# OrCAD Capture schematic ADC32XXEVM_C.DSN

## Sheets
1 SH04 - AMPLIFIER: size B; title: AMPLIFIER; rev: C; note: ADC32XXEVM
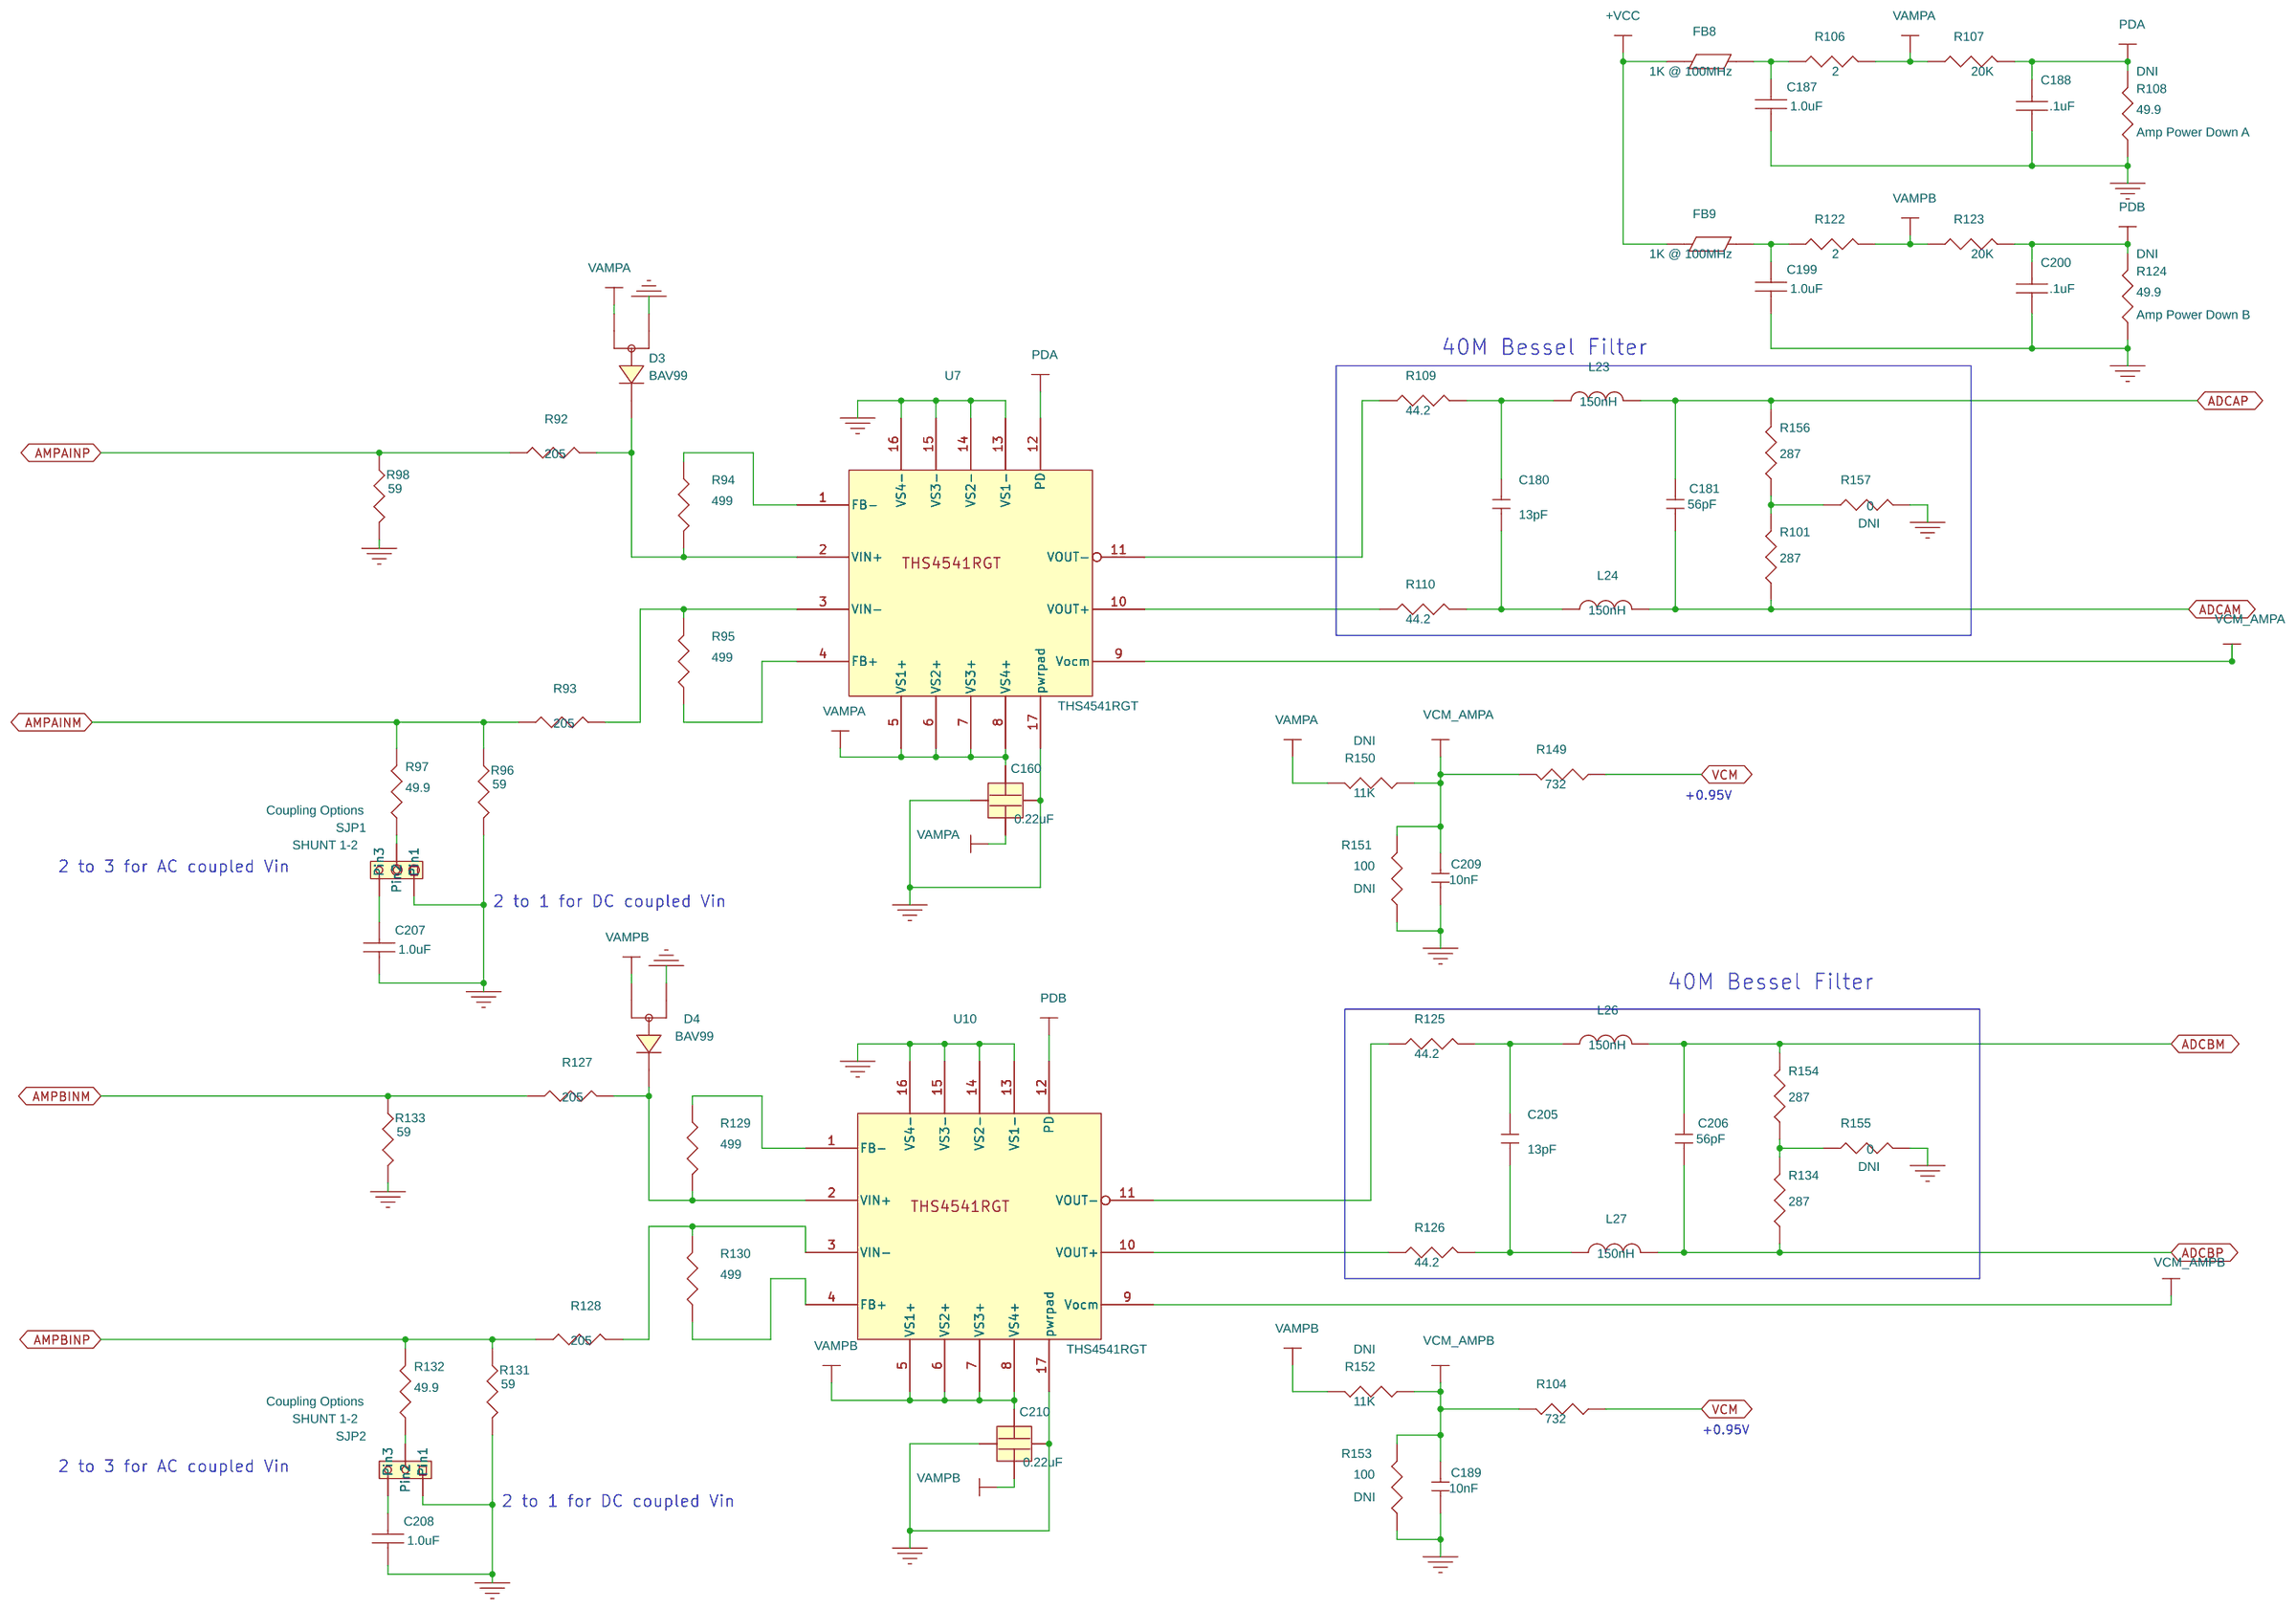
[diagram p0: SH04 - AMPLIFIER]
2 SH01 - COVER: title: ADC34J4X; note: ADC32XX EVM
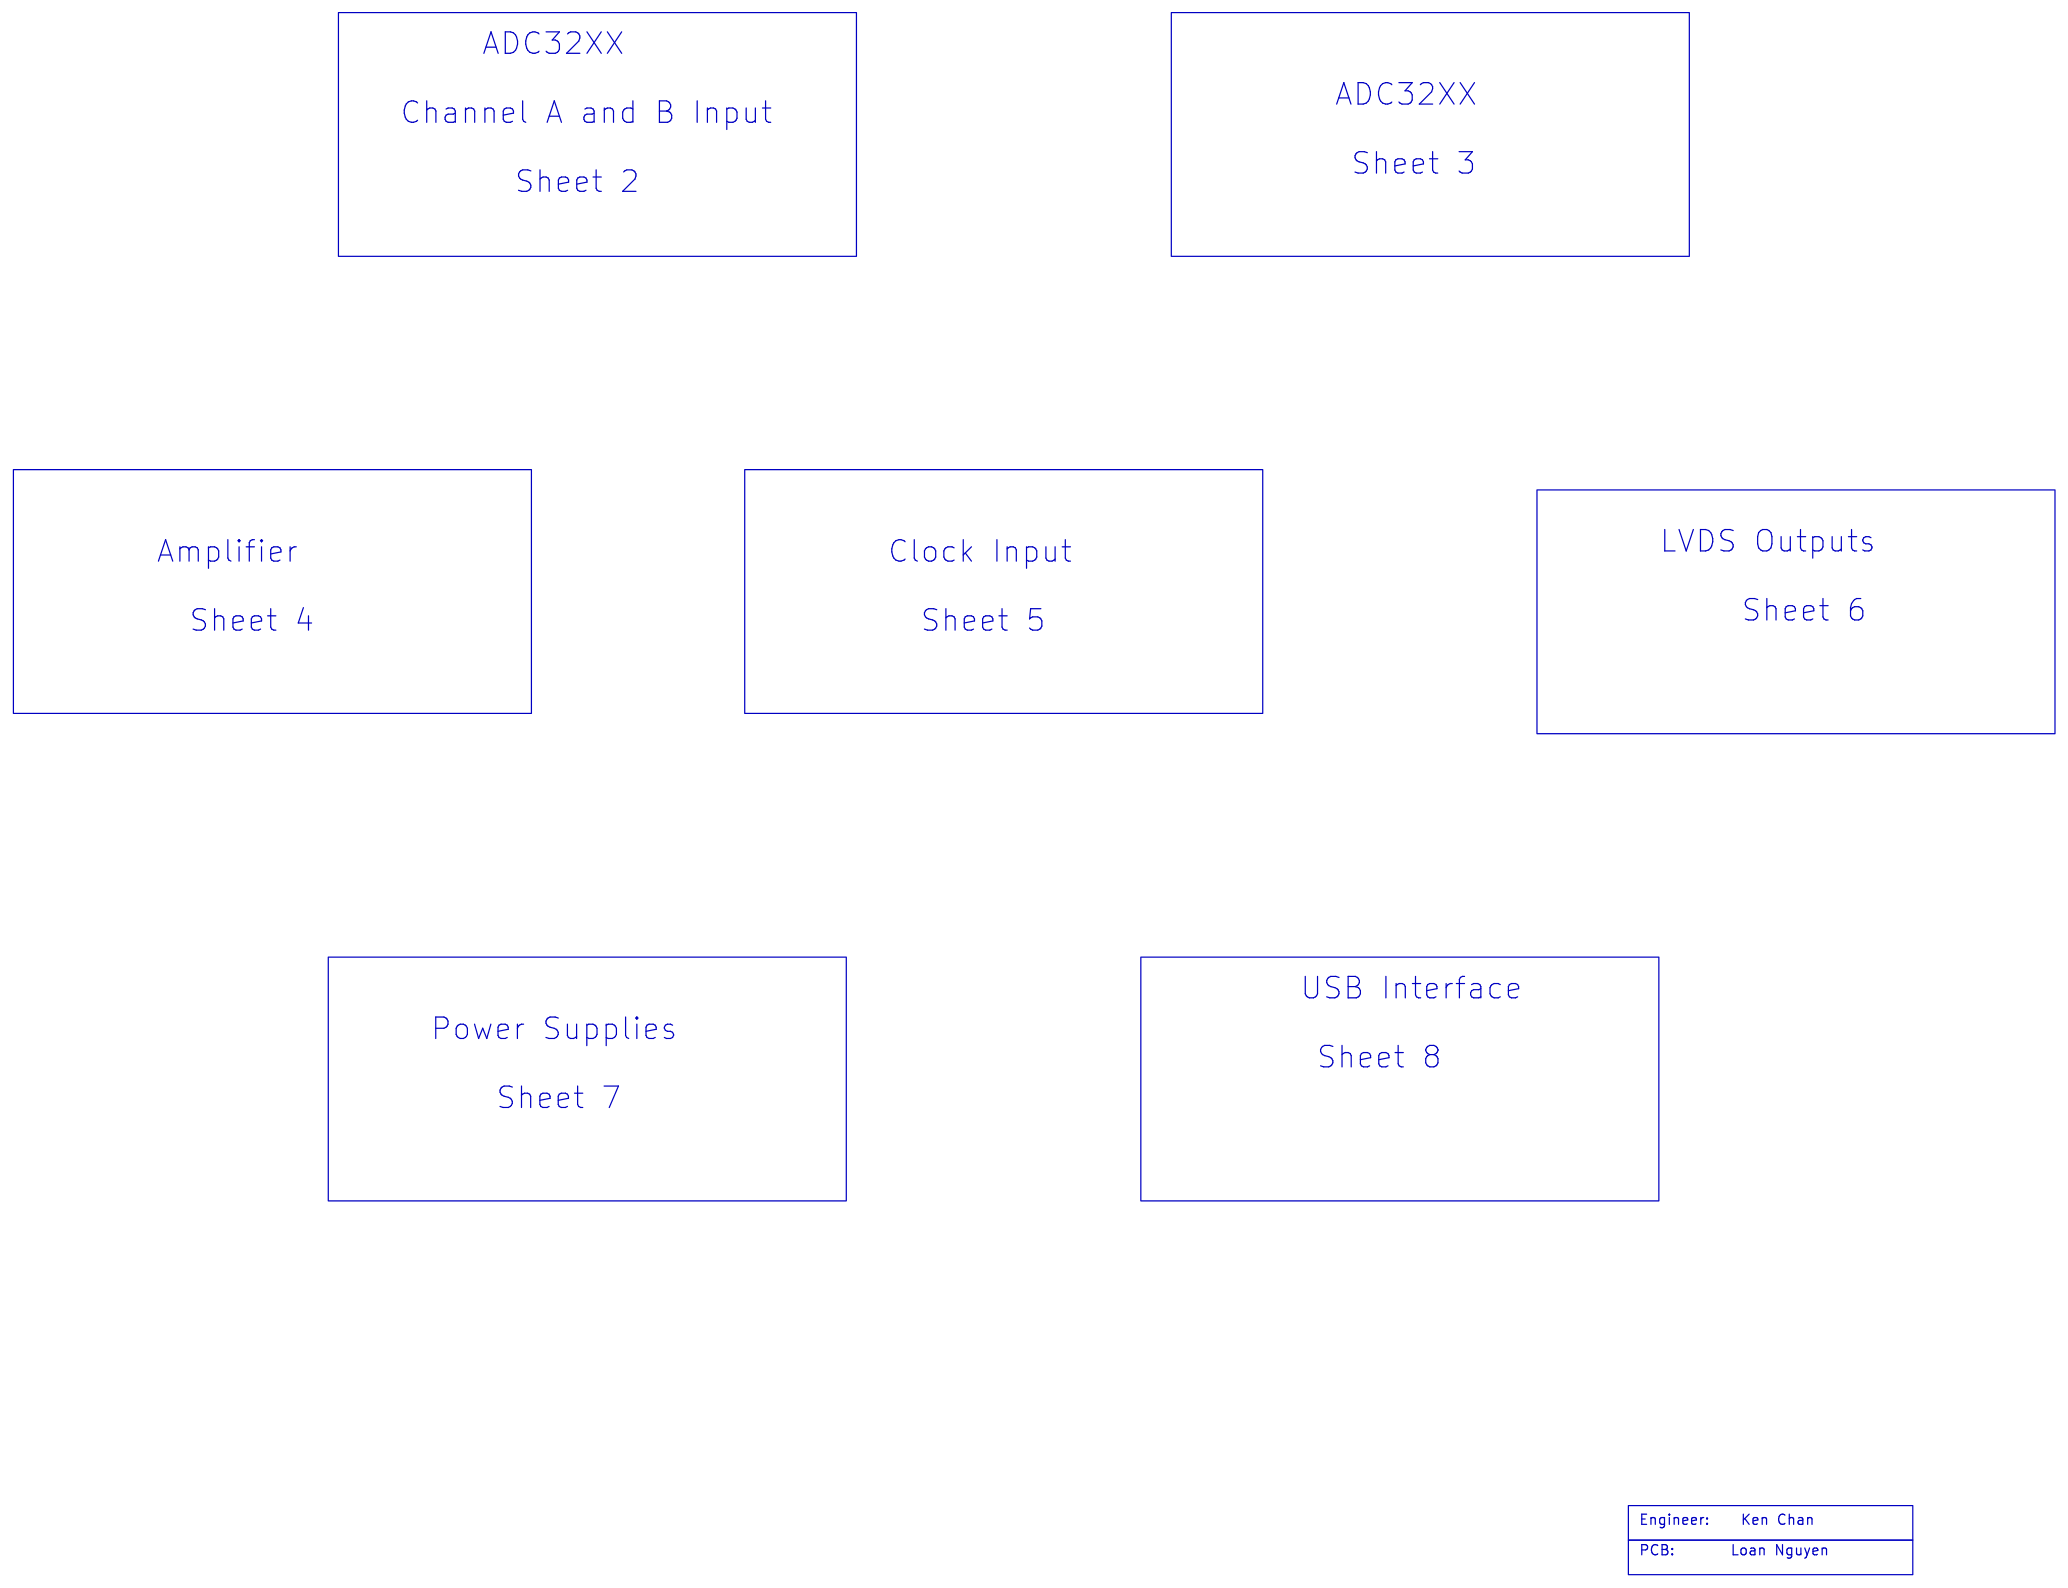
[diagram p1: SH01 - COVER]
3 SH02 - CH A, B INPUT: size B; title: ANALOG IN
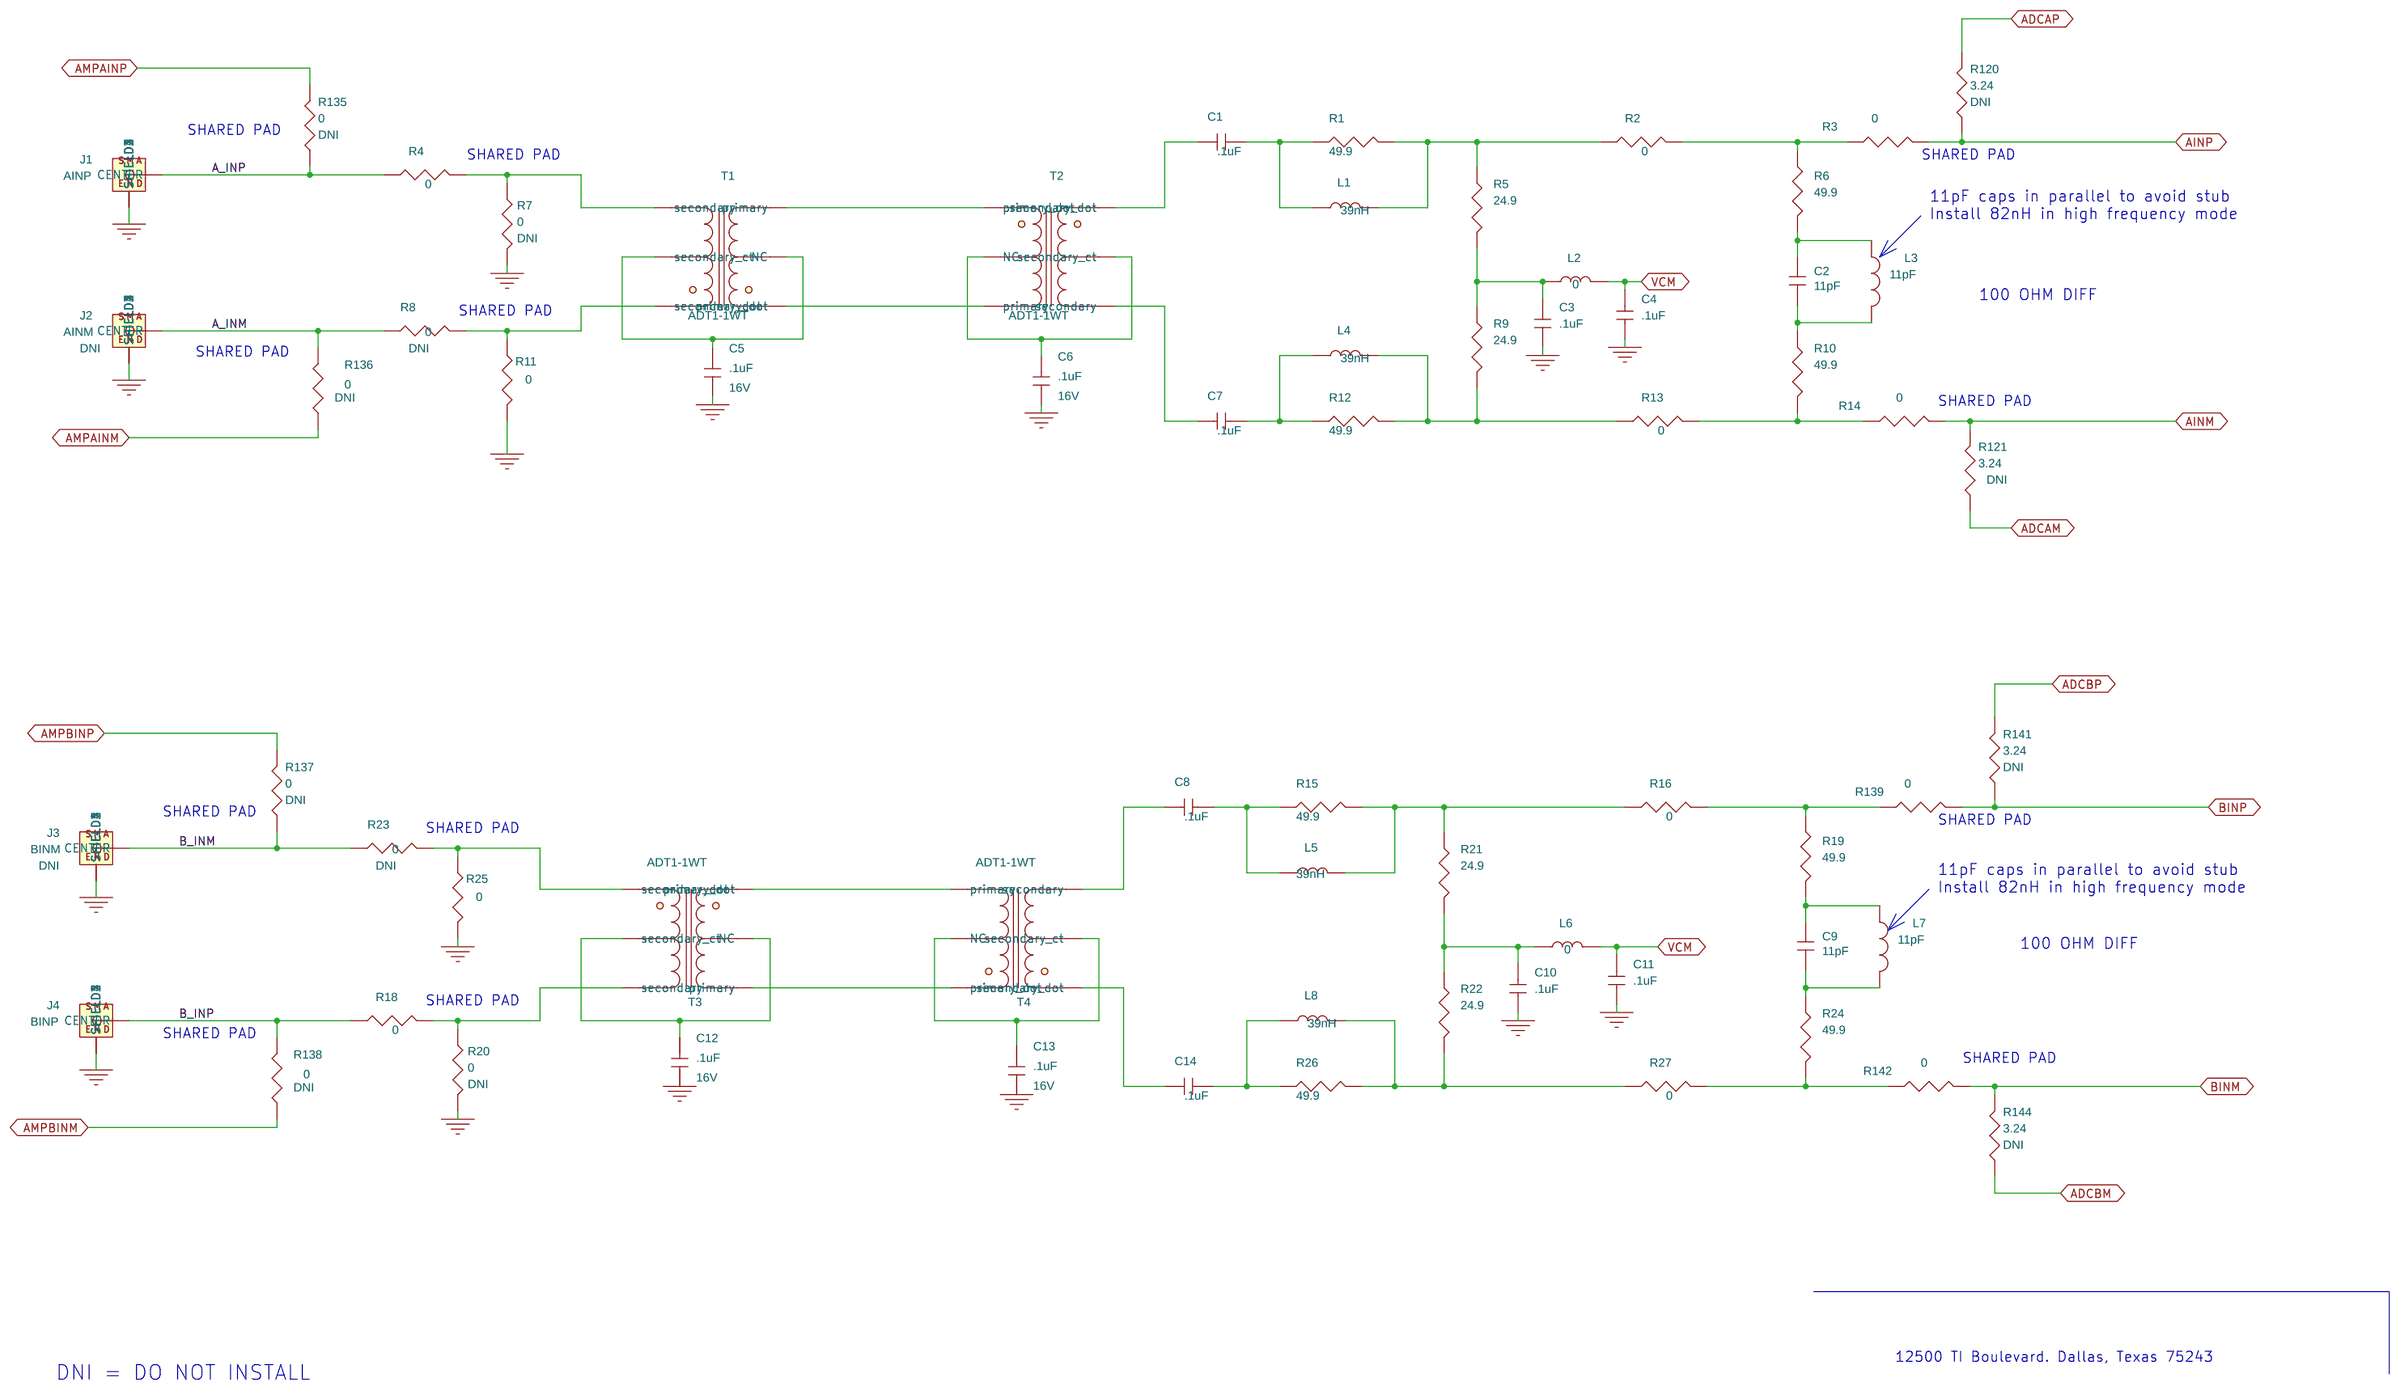
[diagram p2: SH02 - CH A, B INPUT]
4 SH03 - ADC: size B; title: ADC
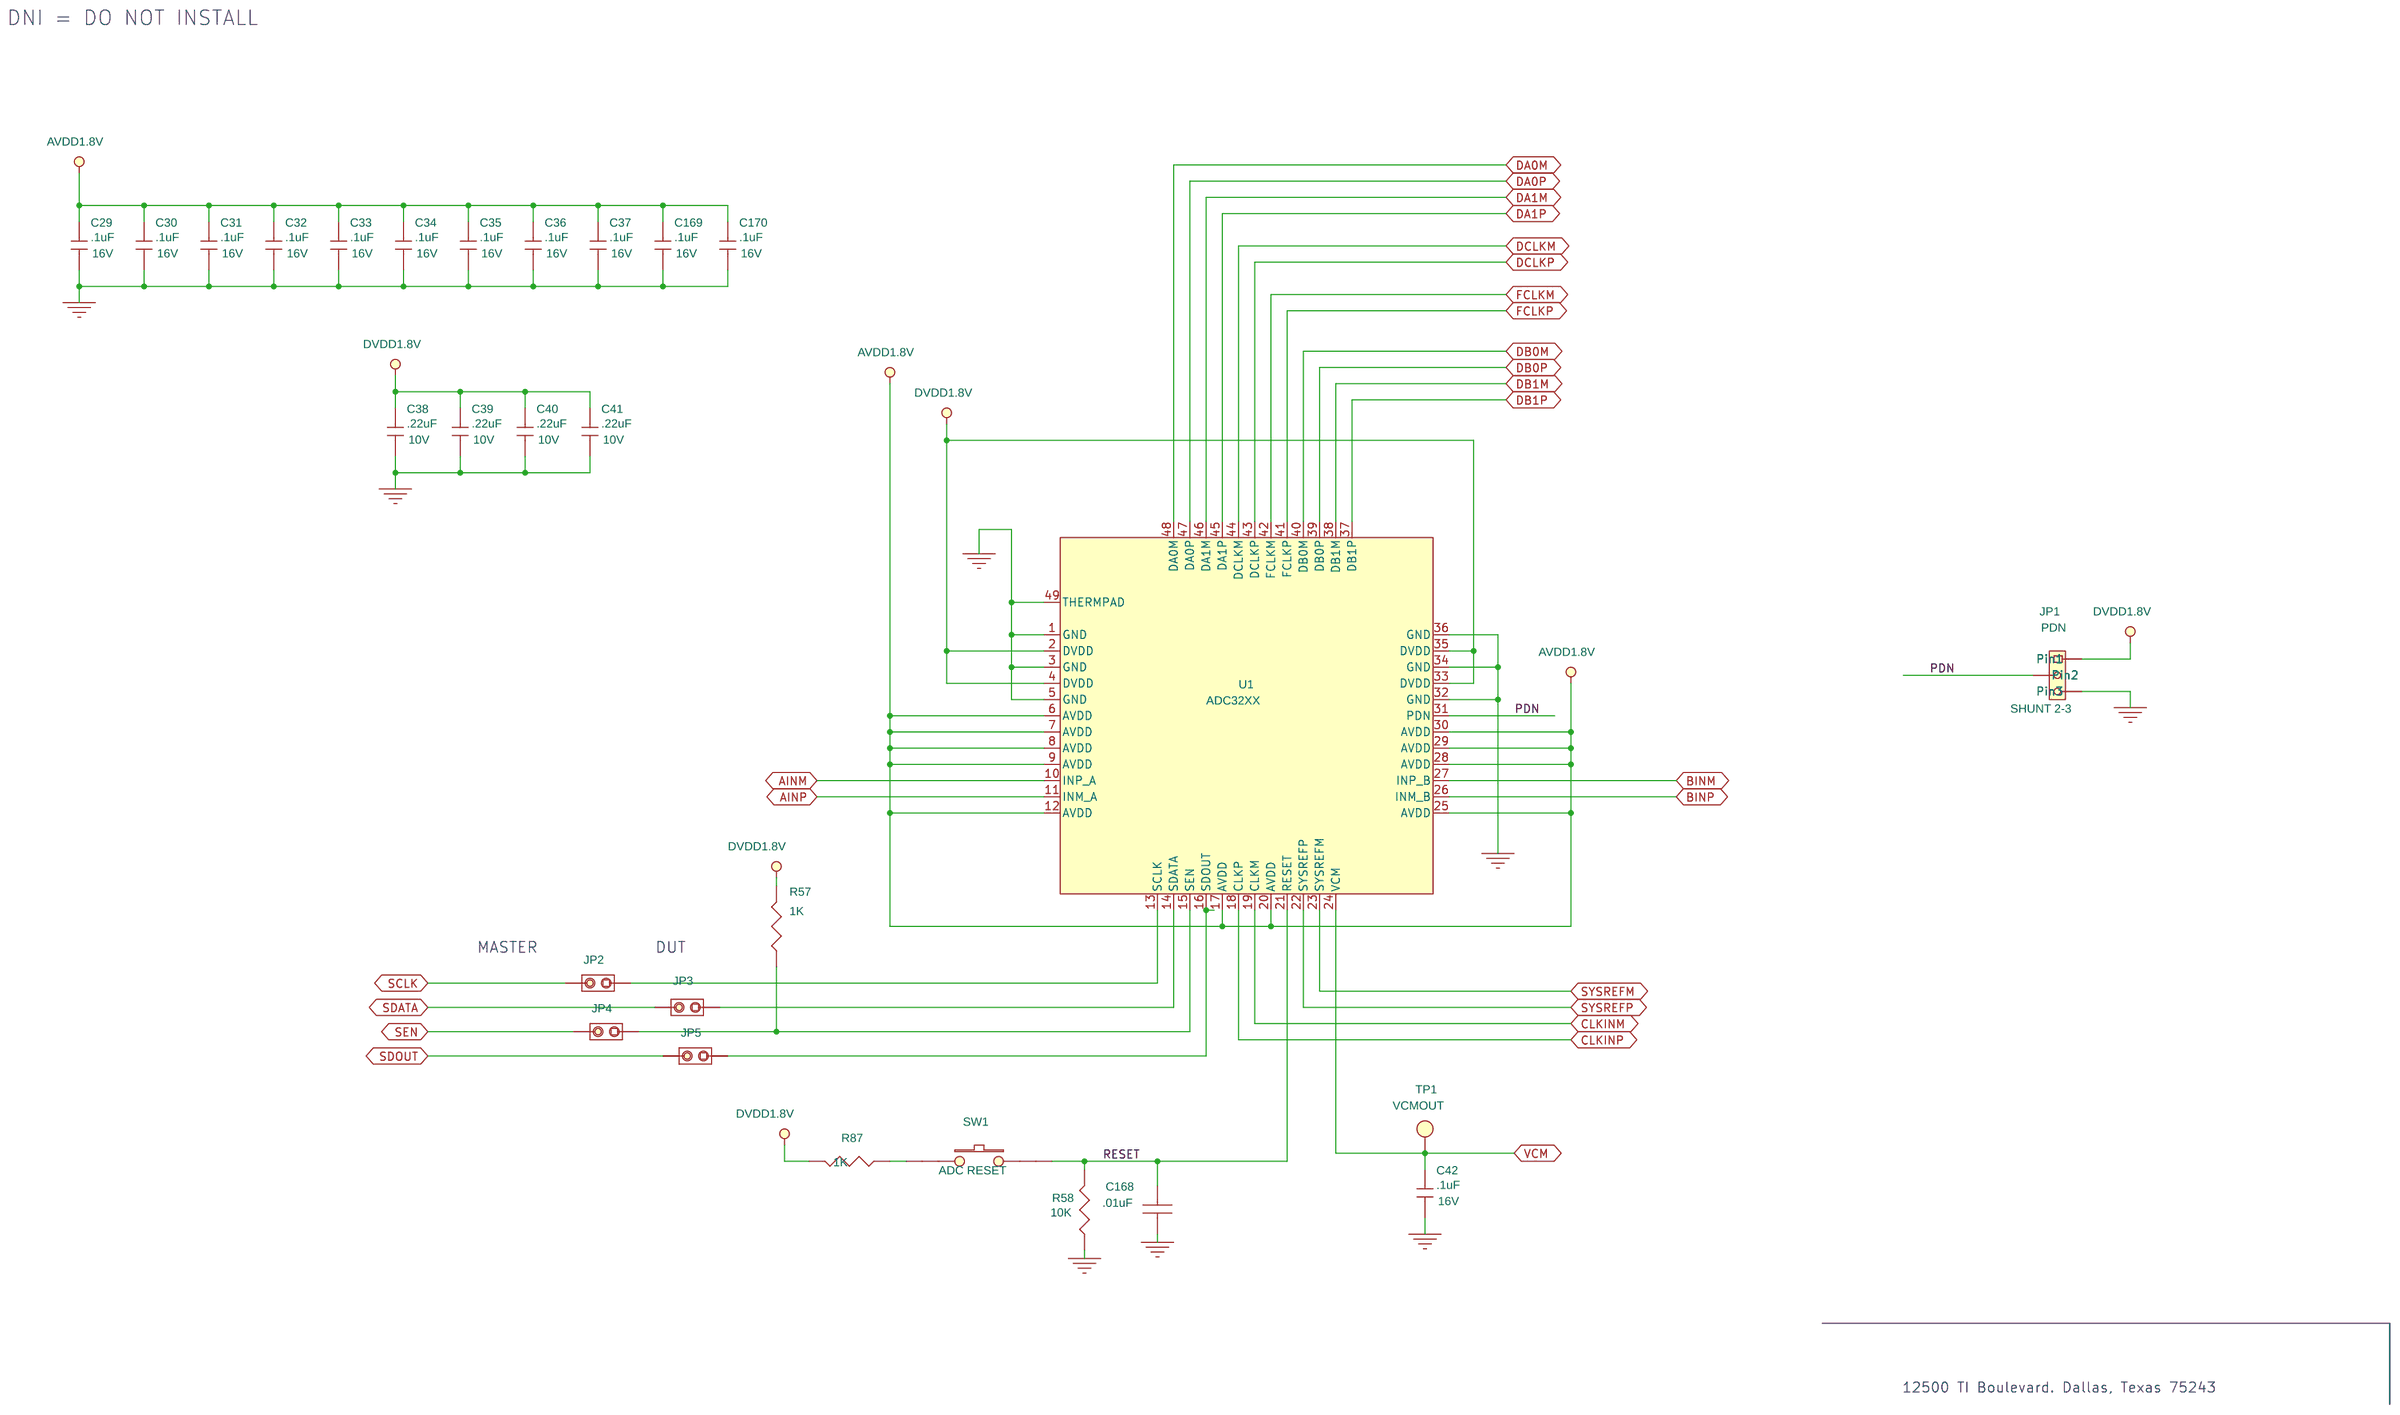
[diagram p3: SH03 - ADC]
5 SH05 - CLOCK INPUT: size B; title: CLOCK INPUT
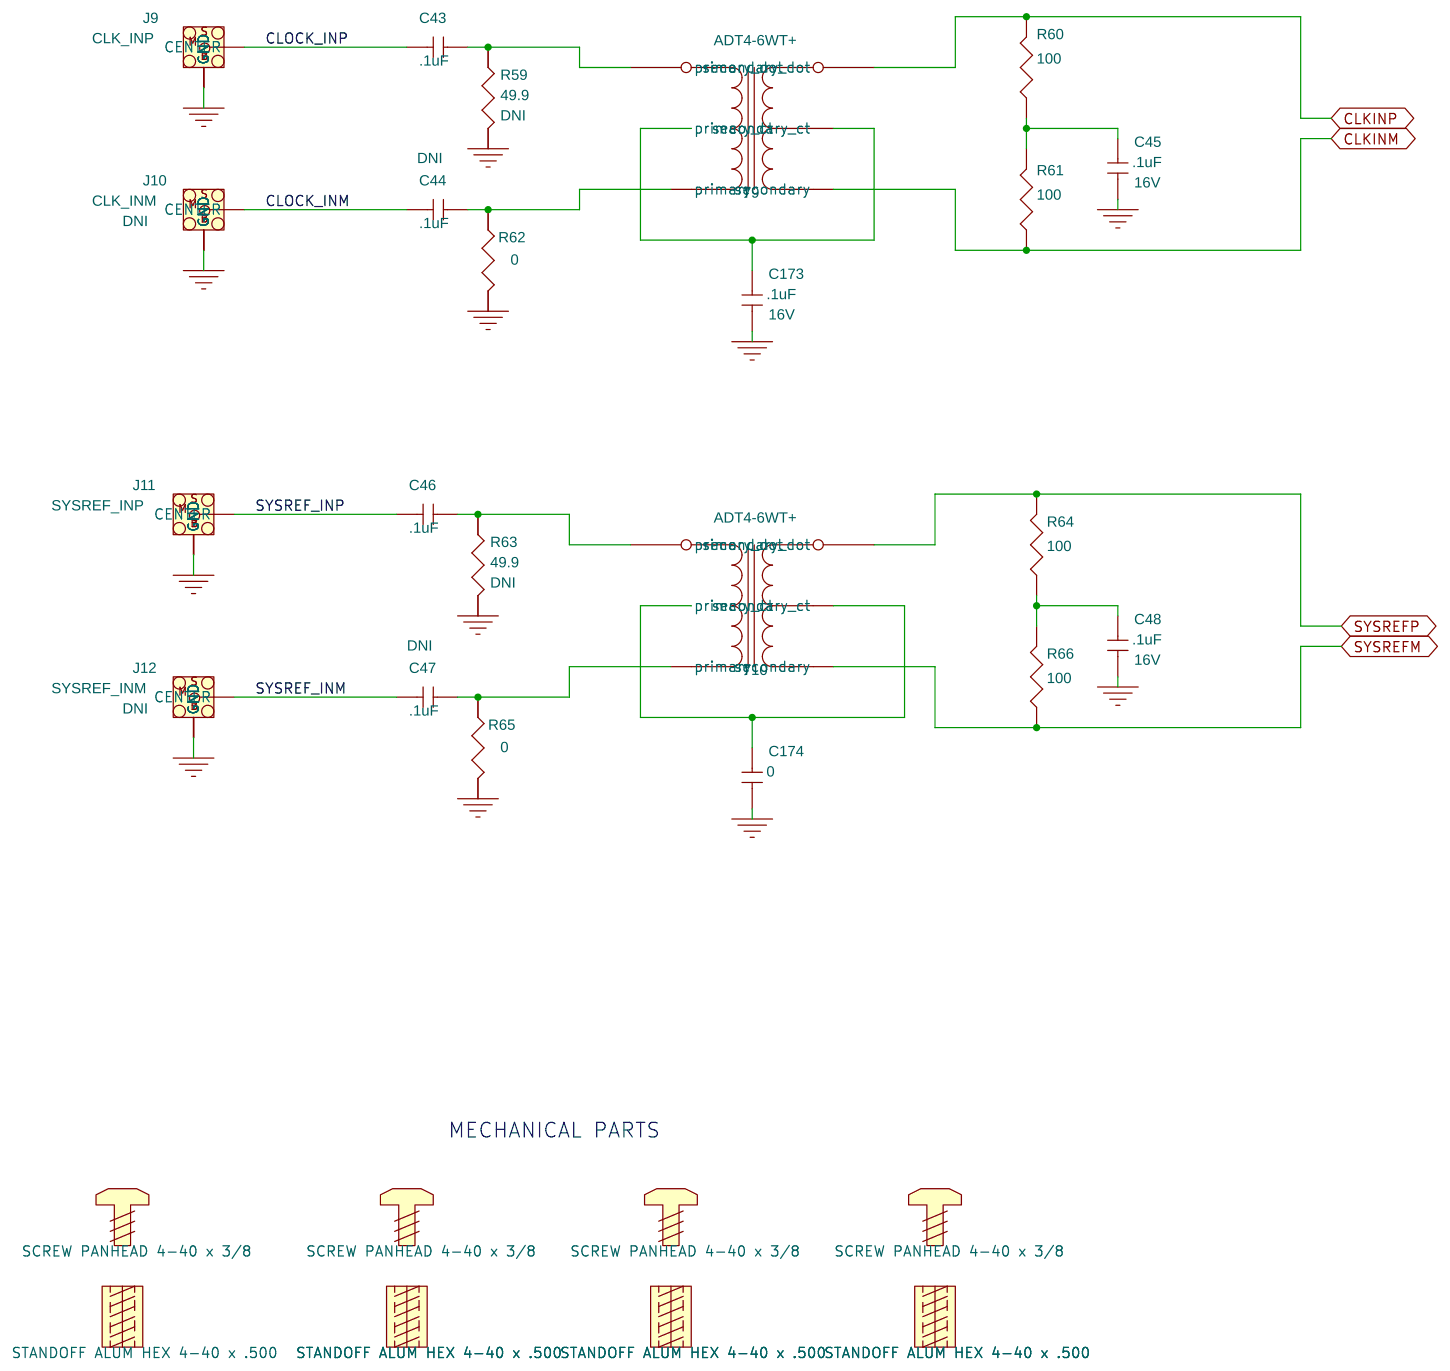
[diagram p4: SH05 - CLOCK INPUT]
6 SH06 - OUTPUT: size B; title: OUTPUT
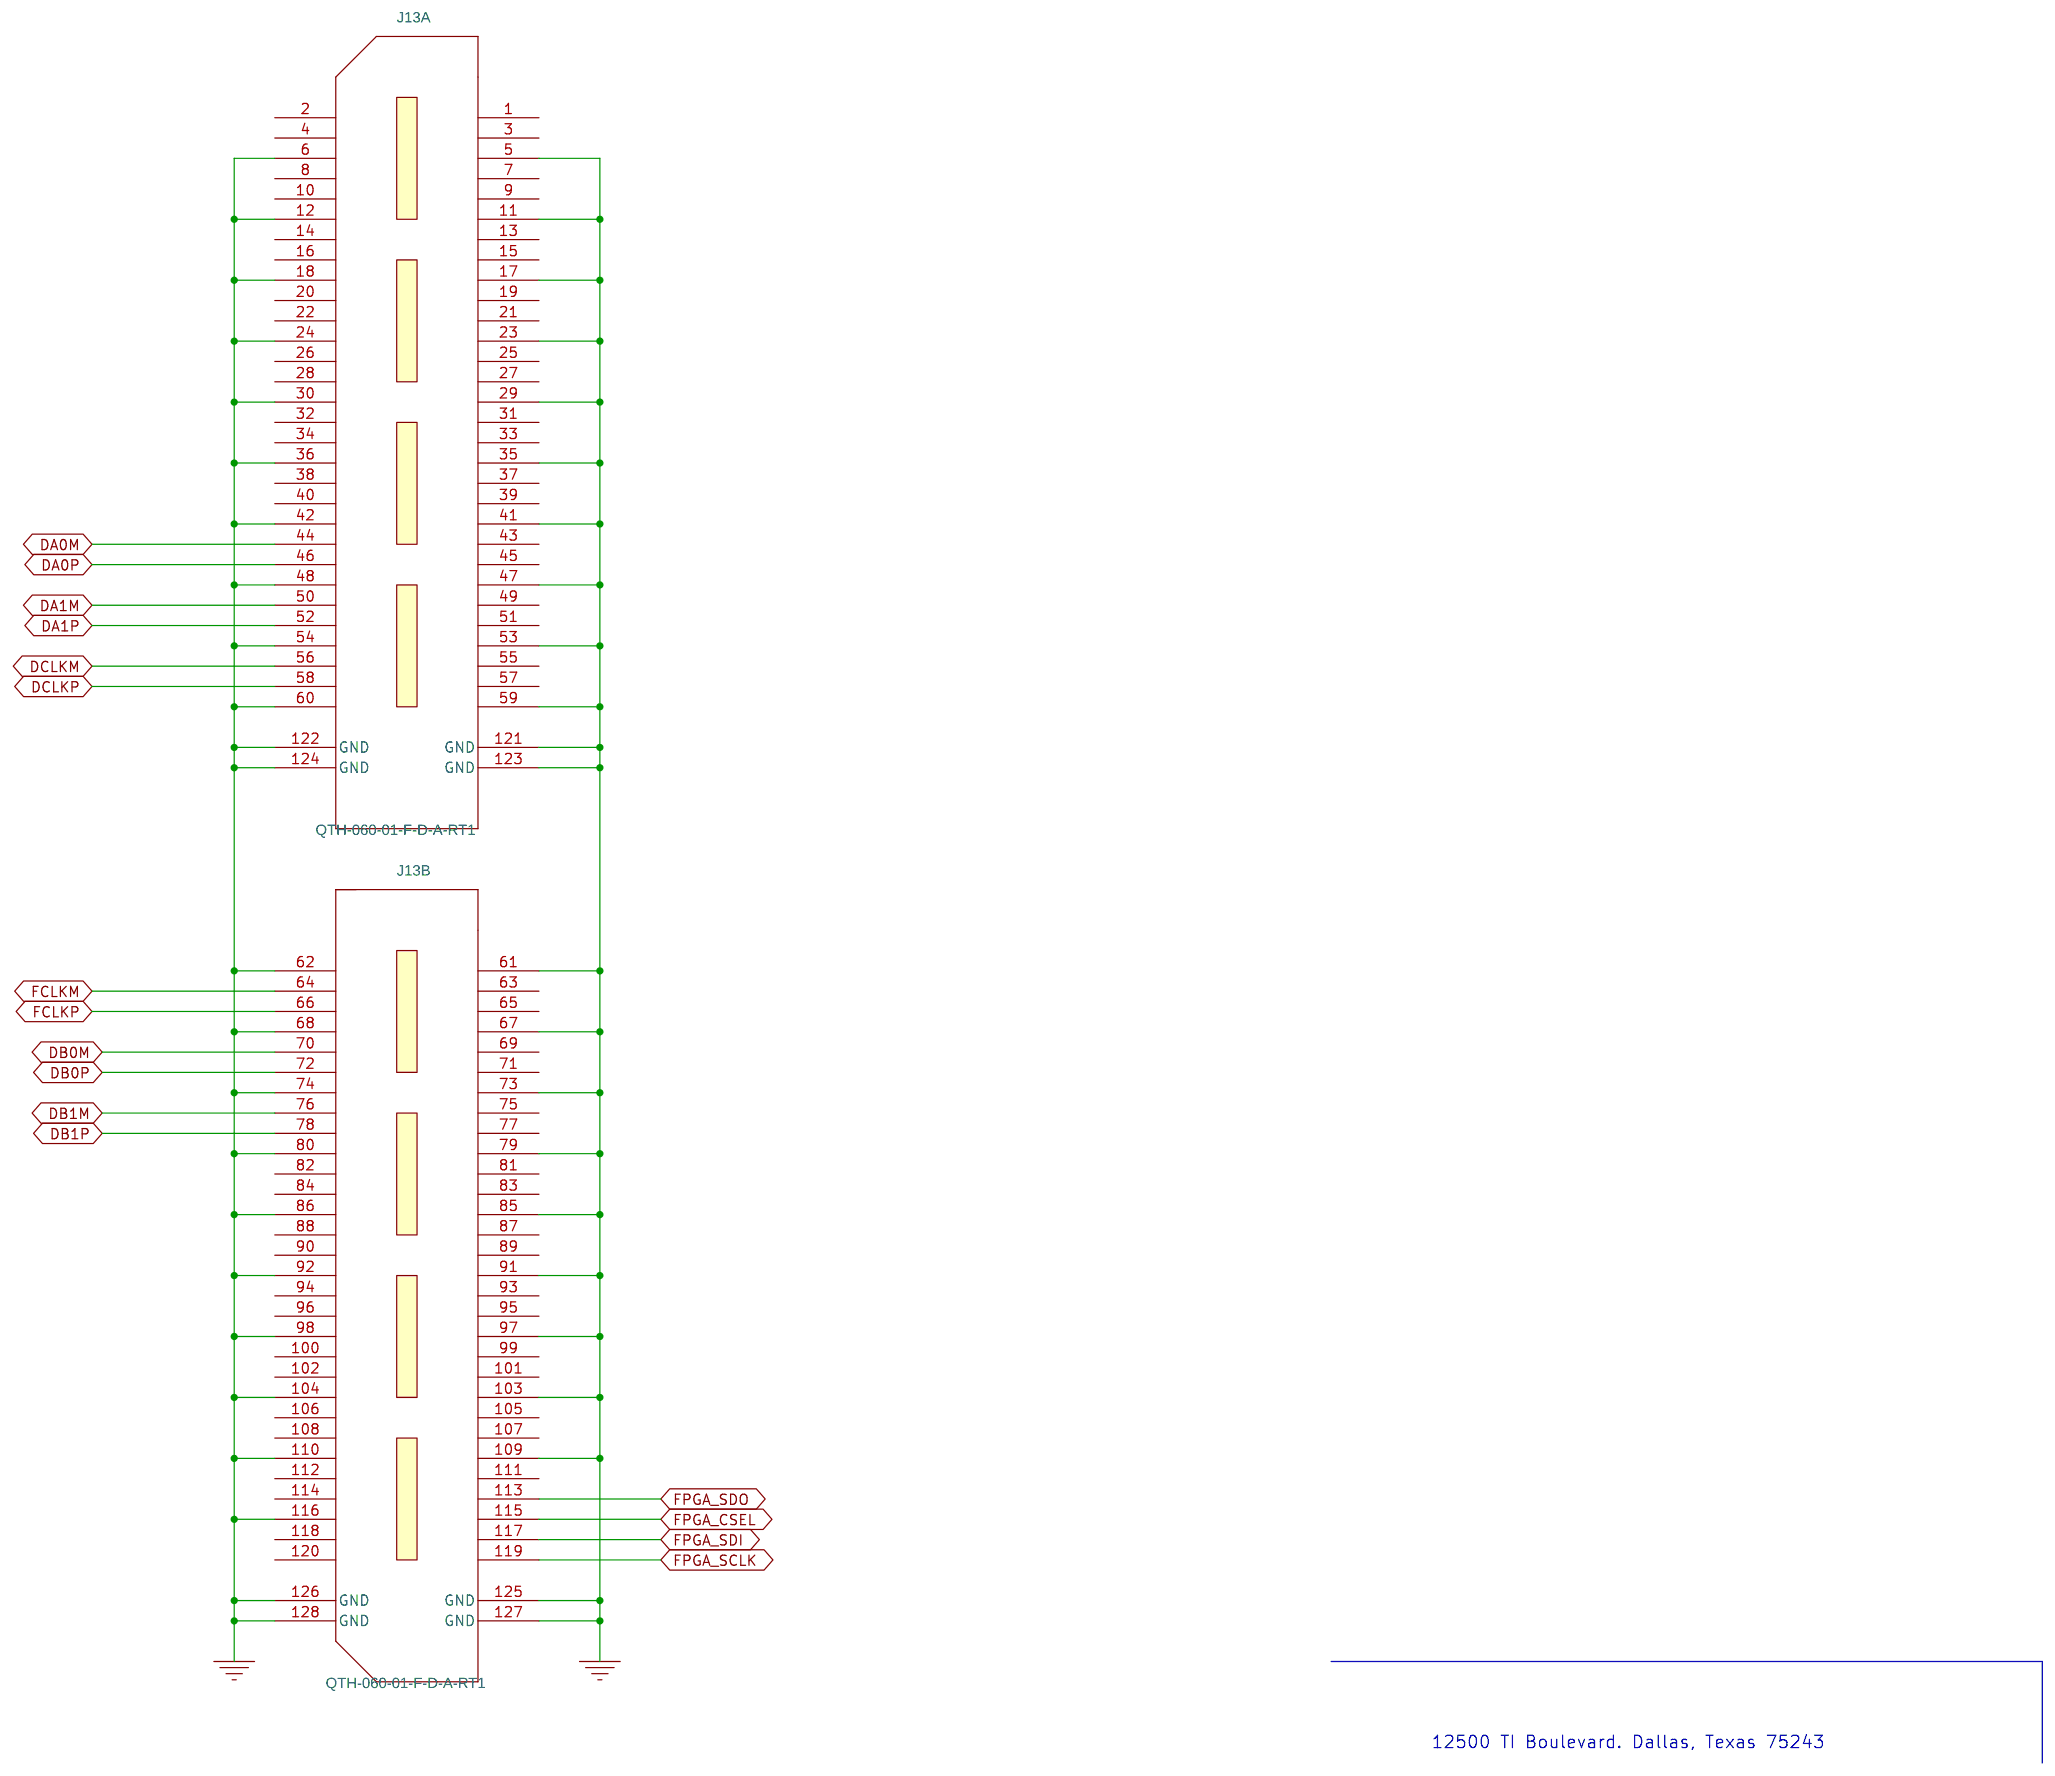
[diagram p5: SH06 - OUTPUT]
7 SH08 - USB: size B; title: USB; rev: B; note: ADC324XEVM
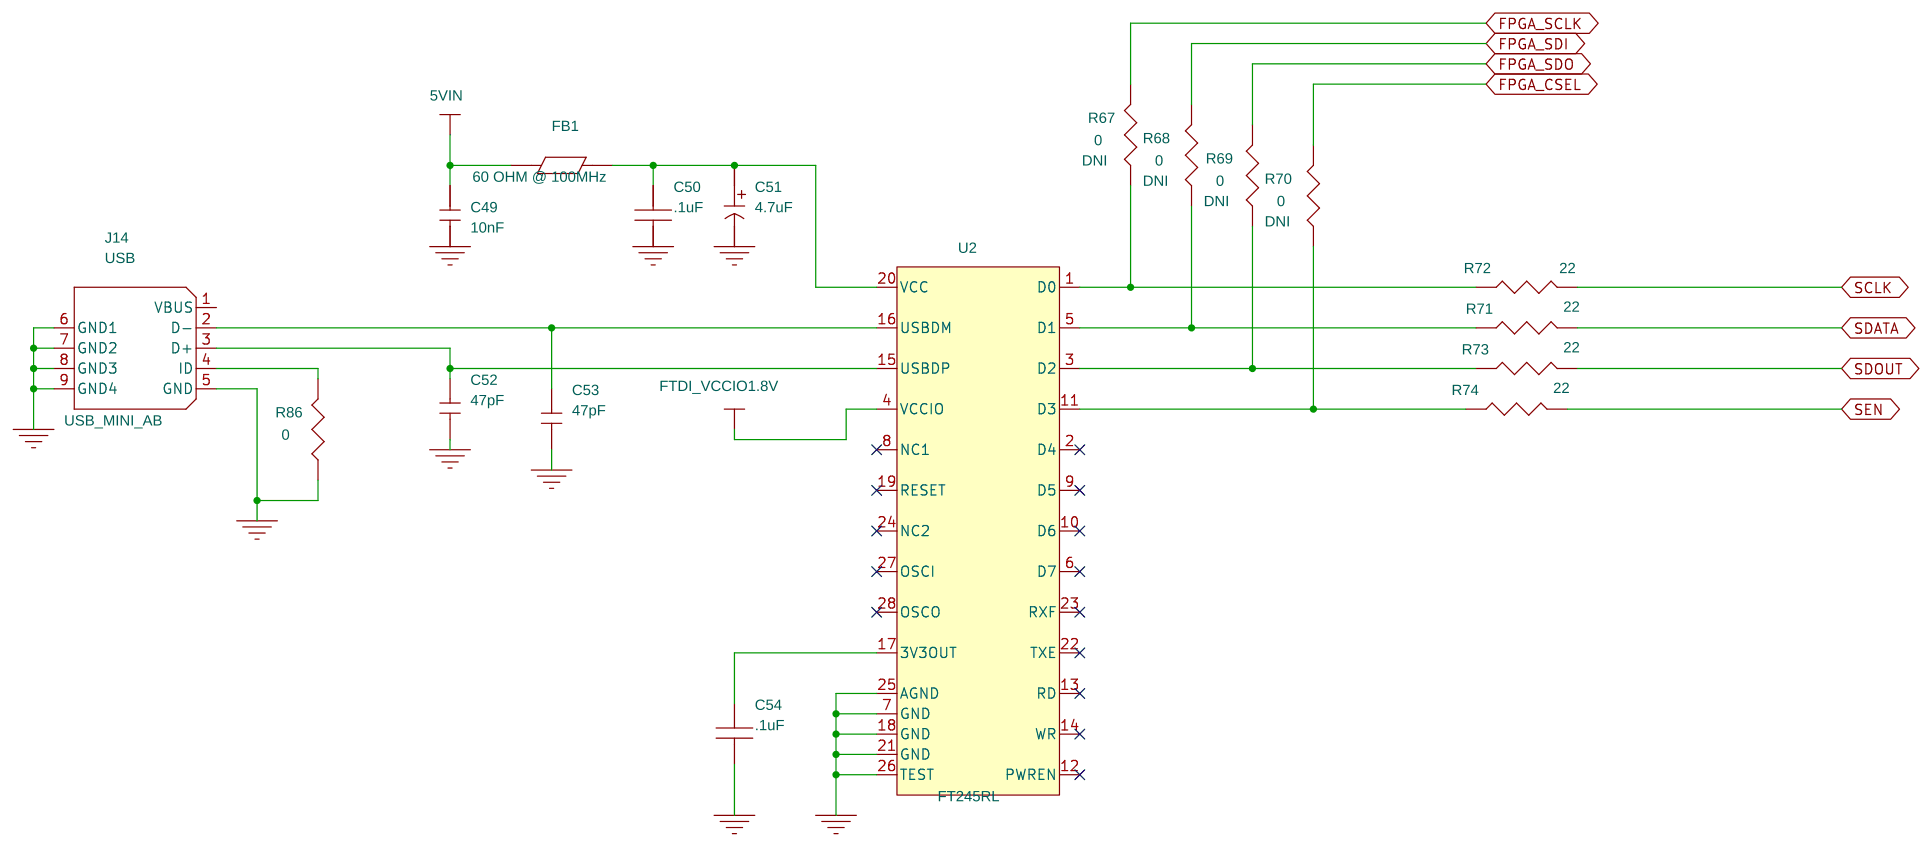
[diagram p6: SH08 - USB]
8 SH07 - POWER SUPPLIES: size B; title: POWER SUPPLIES
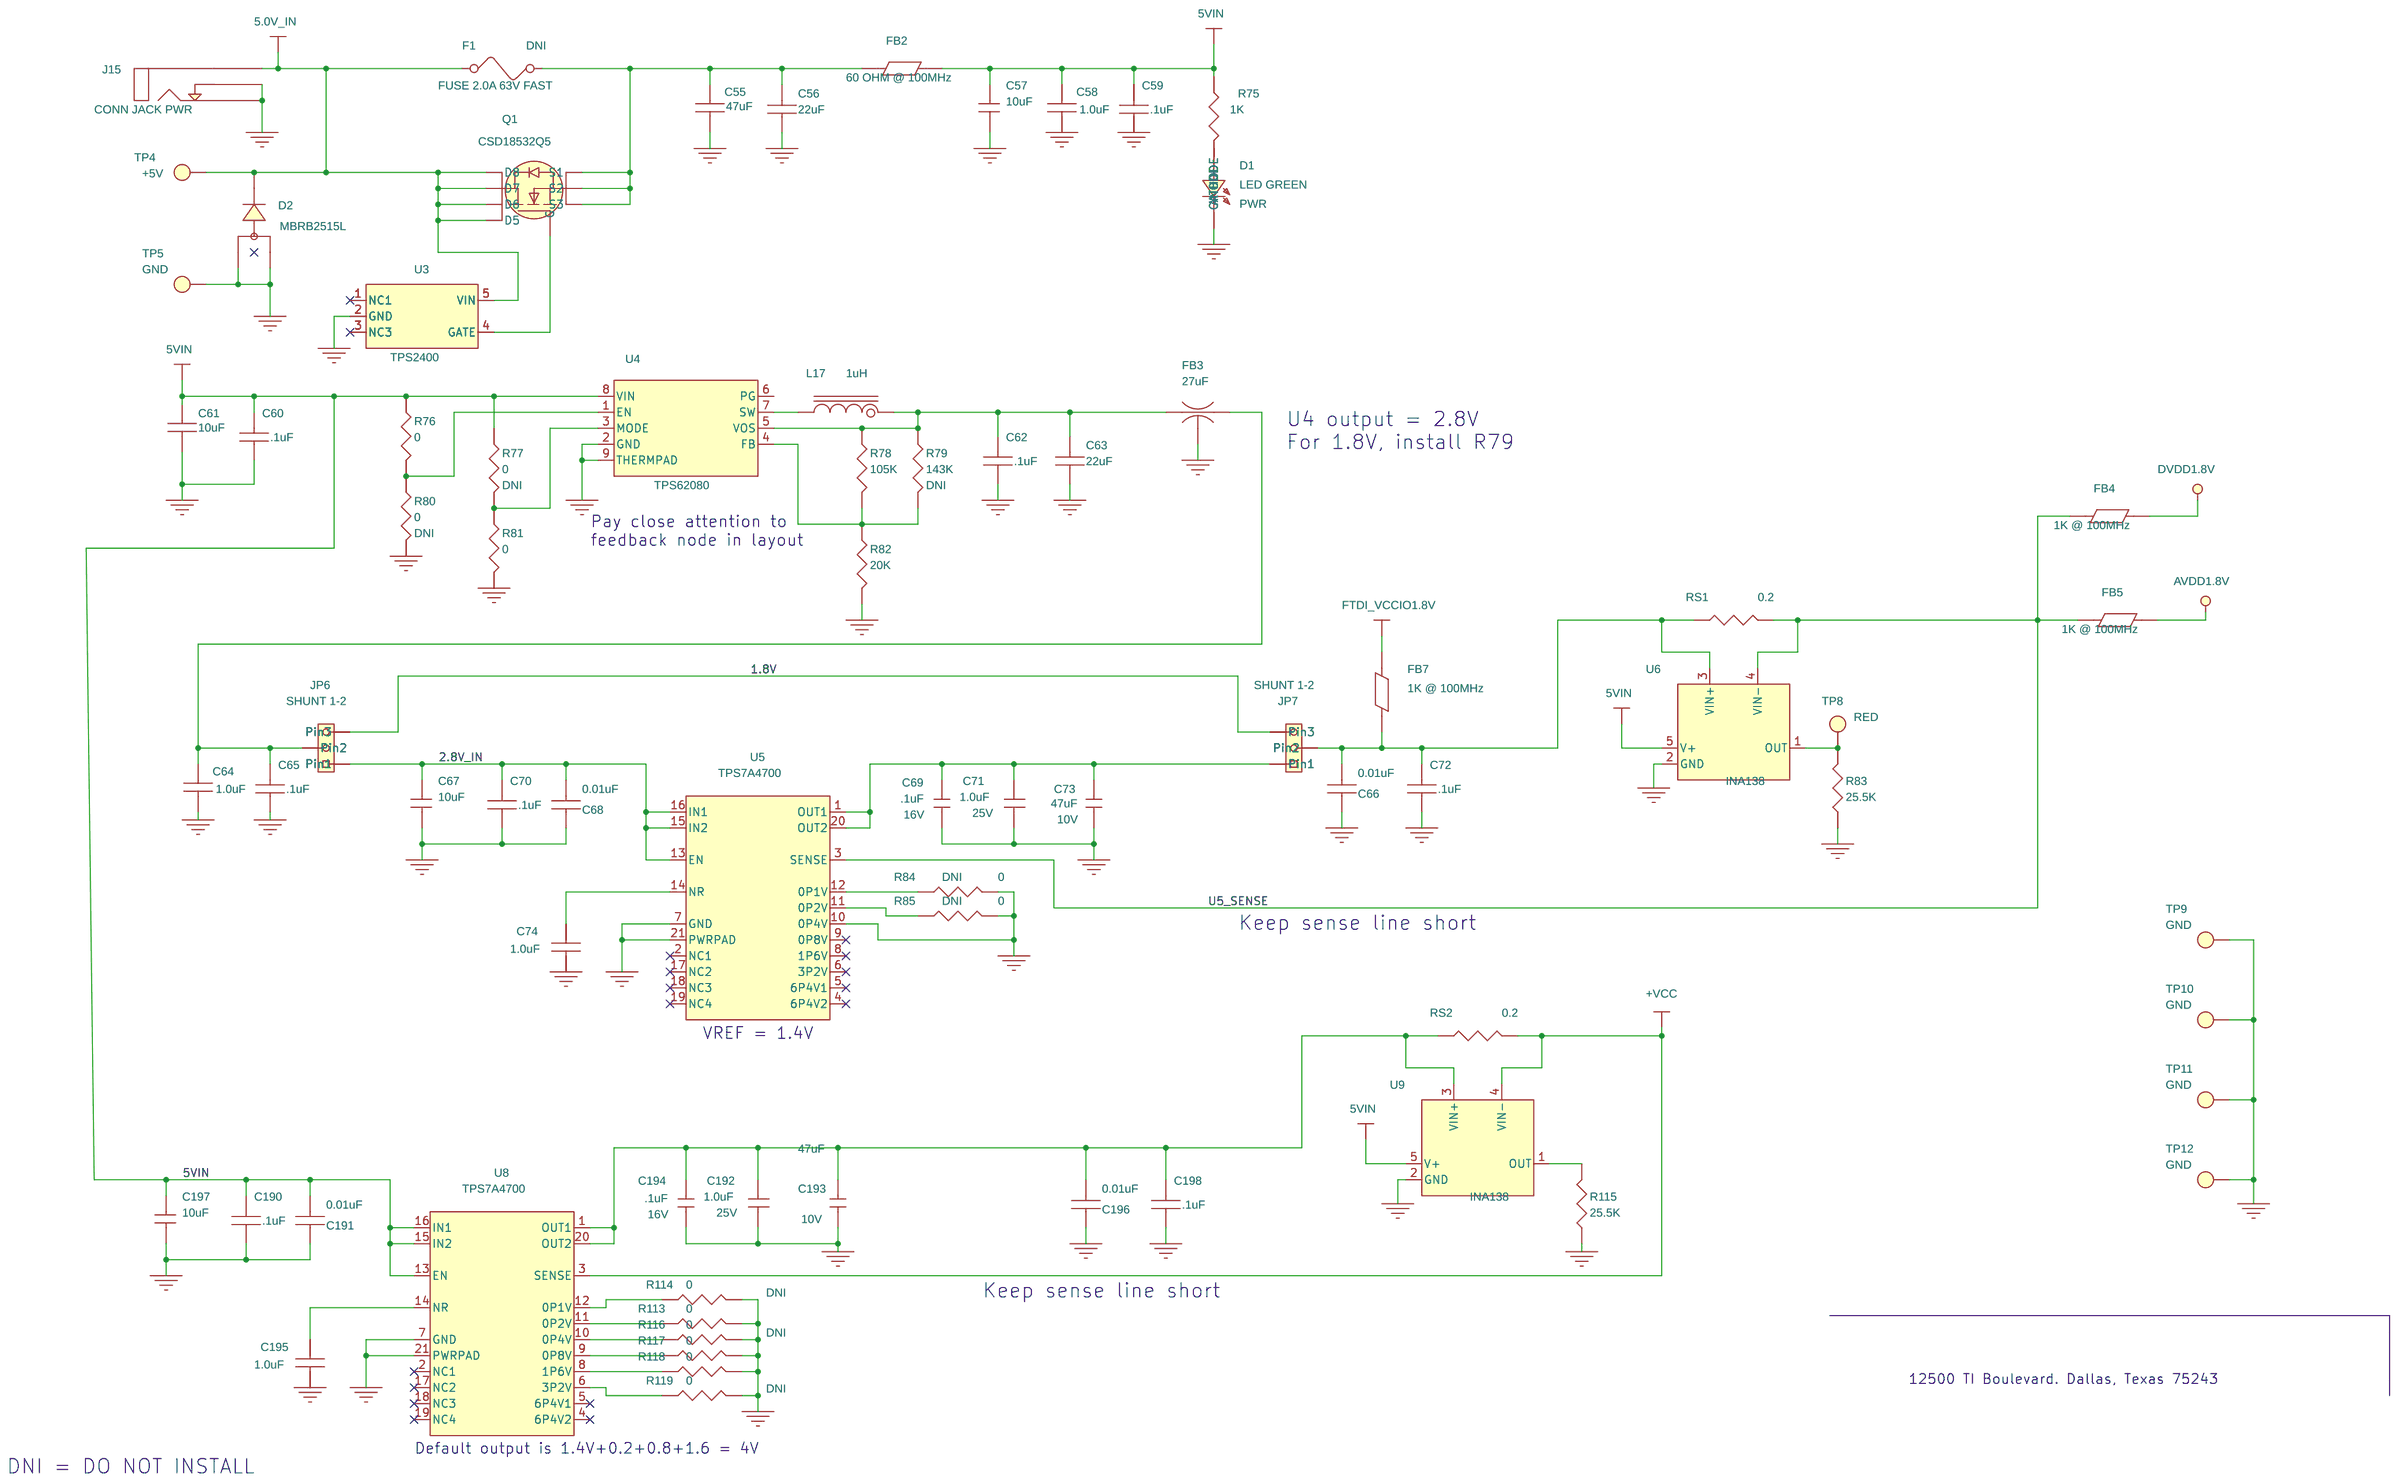
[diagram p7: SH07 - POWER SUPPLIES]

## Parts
sheet SH02 - CH A, B INPUT
C1  .1uF  [0402]
C2  11pF  [0402]
C3  .1uF  [0402]
C4  .1uF  [0402]
C5  .1uF  [0402]
C6  .1uF  [0402]
C7  .1uF  [0402]
C8  .1uF  [0402]
C9  11pF  [0402]
C10  .1uF  [0402]
C11  .1uF  [0402]
C12  .1uF  [0402]
C13  .1uF  [0402]
C14  .1uF  [0402]
J1  SMA_END_RND  [SMA_RECP_250X250]
J2  SMA_END_RND  [SMA_RECP_250X250]
J3  SMA_END_RND  [SMA_RECP_250X250]
J4  SMA_END_RND  [SMA_RECP_250X250]
L1  39nH  [0402]
L2  0  [0402]
L3  11pF  [0603]
L4  39nH  [0402]
L5  39nH  [0402]
L6  0  [0402]
L7  11pF  [0603]
L8  39nH  [0402]
R1  49.9  [0402]
R2  0  [0402]
R3  0  [0402]
R4  0  [0402]
R5  24.9  [0402]
R6  49.9  [0402]
R7  0  [0402]
R8  0  [0402]
R9  24.9  [0402]
R10  49.9  [0402]
R11  0  [0402]
R12  49.9  [0402]
R13  0  [0402]
R14  0  [0402]
R15  49.9  [0402]
R16  0  [0402]
R18  0  [0402]
R19  49.9  [0402]
R20  0  [0402]
R21  24.9  [0402]
R22  24.9  [0402]
R23  0  [0402]
R24  49.9  [0402]
R25  0  [0402]
R26  49.9  [0402]
R27  0  [0402]
R120  3.24  [0402]
R121  3.24  [0402]
R135  0  [0402]
R136  0  [0402]
R137  0  [0402]
R138  0  [0402]
R139  0  [0402]
R141  3.24  [0402]
R142  0  [0402]
R144  3.24  [0402]
T1  ADT1-1WT  [tfmr_6_rf_dual_footprint]
T2  ADT1-1WT  [tfmr_6_rf_dual_footprint]
T3  ADT1-1WT  [tfmr_6_rf_dual_footprint]
T4  ADT1-1WT  [tfmr_6_rf_dual_footprint]
sheet SH03 - ADC
C29  .1uF  [0402]
C30  .1uF  [0402]
C31  .1uF  [0402]
C32  .1uF  [0402]
C33  .1uF  [0402]
C34  .1uF  [0402]
C35  .1uF  [0402]
C36  .1uF  [0402]
C37  .1uF  [0402]
C38  .22uF  [0402]
C39  .22uF  [0402]
C40  .22uF  [0402]
C41  .22uF  [0402]
C42  .1uF  [0402]
C168  .01uF  [0603]
C169  .1uF  [0402]
C170  .1uF  [0402]
JP1  Jumper_1x3  [HDR_THVT_1x3_100_M]
JP2  HEADER_1x2_100_430L  [HDR_THVT_1x2_100_M]
JP3  HEADER_1x2_100_430L  [HDR_THVT_1x2_100_M]
JP4  HEADER_1x2_100_430L  [HDR_THVT_1x2_100_M]
JP5  HEADER_1x2_100_430L  [HDR_THVT_1x2_100_M]
R57  1K  [0402]
R58  10K  [0402]
R87  1K  [0402]
SHN1  SHUNT HEADER
SHN2  SHUNT HEADER
SHN3  SHUNT HEADER
SHN4  SHUNT HEADER
SHN5  SHUNT HEADER
SW1  SW PUSHBUTTON  [SW_RESET_PTS635]
TP1  TP_THVT_060_RND-RED  [TP_THVT_060_RND]
U1  ADC32XX  [QFN48_RGZ_RTC]
sheet SH04 - AMPLIFIER
C160  0.22uF  [C-0603_X2Y]
C180  13pF  [0402]
C181  56pF  [0402]
C187  1.0uF  [0603]
C188  .1uF  [0402]
C189  10nF  [0603]
C199  1.0uF  [0603]
C200  .1uF  [0402]
C205  13pF  [0402]
C206  56pF  [0402]
C207  1.0uF  [0603]
C208  1.0uF  [0603]
C209  10nF  [0603]
C210  0.22uF  [C-0603_X2Y]
D3  BAV99  [SOT_23_321]
D4  BAV99  [SOT_23_321]
FB8  1K @ 100MHz  [0805]
FB9  1K @ 100MHz  [0805]
L23  150nH  [0603]
L24  150nH  [0603]
L26  150nH  [0603]
L27  150nH  [0603]
R92  205  [0402]
R93  205  [0402]
R94  499  [0402]
R95  499  [0402]
R96  59  [0402]
R97  49.9  [0402]
R98  59  [0402]
R101  287  [0402]
R104  732  [0402]
R106  2  [0603]
R107  20K  [0603]
R108  49.9  [0402]
R109  44.2  [0402]
R110  44.2  [0402]
R122  2  [0603]
R123  20K  [0603]
R124  49.9  [0402]
R125  44.2  [0402]
R126  44.2  [0402]
R127  205  [0402]
R128  205  [0402]
R129  499  [0402]
R130  499  [0402]
R131  59  [0402]
R132  49.9  [0402]
R133  59  [0402]
R134  287  [0402]
R149  732  [0402]
R150  11K  [0402]
R151  100  [0402]
R152  11K  [0402]
R153  100  [0402]
R154  287  [0402]
R155  0  [0402]
R156  287  [0402]
R157  0  [0402]
RSHN1  SHUNT RES
RSHN2  SHUNT RES
SJP1  Jumper_1x3_SMT  [SJP3_JUMPER_0603]
SJP2  Jumper_1x3_SMT  [SJP3_JUMPER_0603]
U7  THS4541RGT  [QFN_16_124X124_PWRPAD]
U10  THS4541RGT  [QFN_16_124X124_PWRPAD]
sheet SH05 - CLOCK INPUT
C43  .1uF  [0402]
C44  .1uF  [0402]
C45  .1uF  [0402]
C46  .1uF  [0402]
C47  .1uF  [0402]
C48  .1uF  [0402]
C173  .1uF  [0402]
C174  0  [0402]
J9  SMB_THVT_REC  [SMA_THVT_312x312]
J10  SMB_THVT_REC  [SMA_THVT_312x312]
J11  SMB_THVT_REC  [SMA_THVT_312x312]
J12  SMB_THVT_REC  [SMA_THVT_312x312]
R59  49.9  [0402]
R60  100  [0402]
R61  100  [0402]
R62  0  [0402]
R63  49.9  [0402]
R64  100  [0402]
R65  0  [0402]
R66  100  [0402]
T9  ADT4-6WT+  [tfmr_6_rf_dual_footprint]
T10  ADT4-6WT+  [tfmr_6_rf_dual_footprint]
Z_SCREW1  SCREW PANHEAD 4-40 x 3/8
Z_SCREW2  SCREW PANHEAD 4-40 x 3/8
Z_SCREW3  SCREW PANHEAD 4-40 x 3/8
Z_SCREW4  SCREW PANHEAD 4-40 x 3/8
Z_STANDOFF1  STANDOFF ALUM HEX 4-40 x .500
Z_STANDOFF2  STANDOFF ALUM HEX 4-40 x .500
Z_STANDOFF3  STANDOFF ALUM HEX 4-40 x .500
Z_STANDOFF4  STANDOFF ALUM HEX 4-40 x .500
sheet SH06 - OUTPUT
J13  QTH-060-01-F-D-A-RT1  [CON_SMVT_120POS_QTH_SAMTEC_RT1]  (sections A,B)
sheet SH07 - POWER SUPPLIES
C55  47uF  [1210]
C56  22uF  [1210]
C57  10uF  [0805]
C58  1.0uF  [0603]
C59  .1uF  [0402]
C60  .1uF  [0402]
C61  10uF  [0805]
C62  .1uF  [0402]
C63  22uF  [1210]
C64  1.0uF  [0603]
C65  .1uF  [0402]
C66  0.01uF  [0402]
C67  10uF  [0805]
C68  0.01uF  [0402]
C69  .1uF  [0402]
C70  .1uF  [0402]
C71  1.0uF  [0603]
C72  .1uF  [0402]
C73  47uF  [0805]
C74  1.0uF  [0603]
C190  .1uF  [0402]
C191  0.01uF  [0402]
C192  1.0uF  [0603]
C193  47uF  [0805]
C194  .1uF  [0402]
C195  1.0uF  [0603]
C196  0.01uF  [0402]
C197  10uF  [0805]
C198  .1uF  [0402]
D1  LED GREEN  [LED_1206]
D2  MBRB2515L  [DIODE_MBRB2515L]
F1  FUSE 2.0A 63V FAST  [1206]
FB2  60 OHM @ 100MHz  [1206]
FB3  27uF  [1206_BEAD_NFM31P]
FB4  1K @ 100MHz  [1806]
FB5  1K @ 100MHz  [1806]
FB7  1K @ 100MHz  [1806]
J15  CONN JACK PWR  [CON_RAPC722_JACK_THVT_3]
JP6  HDR, THVT, 3POS  [HDR_THVT_1X3_100_M]
JP7  HDR, THVT, 3POS  [HDR_THVT_1X3_100_M]
L17  1uH  [IND_SM_LQH44P_1515]
Q1  CSD18532Q5  [SON_Q5B_8]
R75  1K  [0402]
R76  0  [0402]
R77  0  [0402]
R78  105K  [0402]
R79  143K  [0402]
R80  0  [0402]
R81  0  [0402]
R82  20K  [0402]
R83  25.5K  [0402]
R84  0  [0402]
R85  0  [0402]
R113  0  [0402]
R114  0  [0402]
R115  25.5K  [0402]
R116  0  [0402]
R117  0  [0402]
R118  0  [0402]
R119  0  [0402]
RS1  0.2  [0805]
RS2  0.2  [0805]
SHN6  SHUNT HEADER
SHN7  SHUNT HEADER
TP4  Testloop_Red  [testpoint_62dia]
TP5  Testloop_Black  [testpoint_62dia]
TP8  RED  [TP_THVT_100_RND]
TP9  Testloop_Black  [testpoint_62dia]
TP10  Testloop_Black  [testpoint_62dia]
TP11  Testloop_Black  [testpoint_62dia]
TP12  Testloop_Black  [testpoint_62dia]
U3  TPS2400  [DBV5]
U4  TPS62080  [SON_DSG_8]
U5  TPS7A4700  [qfn20_rgw_p65pitch]
U6  INA138  [DBV5]
U8  TPS7A4700  [qfn20_rgw_p65pitch]
U9  INA138  [DBV5]
sheet SH08 - USB
C49  10nF  [0603]
C50  .1uF  [0402]
C51  4.7uF  [tant_a]
C52  47pF  [0603]
C53  47pF  [0603]
C54  .1uF  [0402]
FB1  60 OHM @ 100MHz  [1206]
J14  USB_MINI_AB  [CON_SMRT_USBMNE20_F]
R67  0  [0402]
R68  0  [0402]
R69  0  [0402]
R70  0  [0402]
R71  22  [0402]
R72  22  [0402]
R73  22  [0402]
R74  22  [0402]
R86  0  [0402]
U2  FT245RL  [ssop_28_413x221_26]

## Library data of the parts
C1 C7 C8 C14 = CAP_0402_0.1uF: Mfr_Name: MURATA; Mfr_Part_Number: GRM155R71C104KA88D; TOL: 10%; VOLTAGE: 16V
C2 C9 = CAP0603: Mfr_Name: TDK; Mfr_Part_Number: CBR04C110F5GAC; TOL: 1%; VOLTAGE: 50V
C3 C4 C10 C11 = CAP_0402_0.1uF_H: Mfr_Part_Number: GRM155R71C104KA88D; TOL: 10%; VOLTAGE: 16V
C5 C6 C12 C13 C45 C48 C69 C173 C194 = CAP0603: Mfr_Name: MURATA; Mfr_Part_Number: GRM155R71C104KA88D; TOL: 10%; Voltage: 16V
J1 = SMA-END_PLUG_ROUND: Mfr_Name: Johnson Components; Mfr_Part_Number: 142-0711-821; PART_NUMBER: 142-0711-821; TI_Silktext: AINP
J2 = SMA-END_PLUG_ROUND: Mfr_Name: Johnson Components; Mfr_Part_Number: 142-0711-821; Note: DNI; PART_NUMBER: 142-0711-821; TI_Silktext: AINM
J3 = SMA-END_PLUG_ROUND: Mfr_Name: Johnson Components; Mfr_Part_Number: 142-0711-821; Note: DNI; PART_NUMBER: 142-0711-821; TI_Silktext: BINM
J4 = SMA-END_PLUG_ROUND: Mfr_Name: Johnson Components; Mfr_Part_Number: 142-0711-821; PART_NUMBER: 142-0711-821; TI_Silktext: BINP
L1 L4 L5 L8 = IND_0402: Mfr_Name: PANASONIC; Mfr_Part_Number: 0402HP-39NXJLU
L2 L6 = IND_0402_H: Mfr_Name: PANASONIC; Mfr_Part_Number: ERJ-2GE0R00X
L3 L7 = IND0603: Mfr_Name: Kemet; Mfr_Part_Number: CBR06C110FAGAC; TOL: 1%
R1 R6 R10 R12 R15 R19 R24 R26 = Res_0402_49.9: Mfr_Part_Number: ERJ-2RKF49R9X; TOL: 1%
R2 R13 R16 R27 = Res_0402_Zero
R3 R14 R139 R142 = Res_0402_4.99: Mfr_Name: Panasonic; Mfr_Part_Number: ERJ-2GE0R00X
R4 R18 R25 R62 R65 R86 R113 R117 R118 = R: Mfr_Name: Panasonic; Mfr_Part_Number: ERJ-2GE0R00X; TOL: 5%
R5 R9 R21 R22 = Res_0402_24.9
R7 R8 R20 R23 R155 R157 = RES0603: GROUP: Not Installed; Mfr_Name: Panasonic; Mfr_Part_Number: ERJ-2GE0R00X; Note: DNI; TOL: 5%
R11 = R: Mfr_Name: Panasonic; Mfr_Part_Number: ERJ-2GE0R00X
R120 R121 R141 R144 = Res_0402_Zero: Mfr_Name: Vishay Dale; Mfr_Part_Number: CRCW04023R24FKED; Note: DNI
R135-R138 = Res_0402_Zero: Note: DNI
T1-T4 = TFMR_6_WBC1-1TLB: Mfr_Name: MiniCircuits; Mfr_Part_Number: ADT1-1WT+
C29-C37 C42 C43 C46 C169 C170 = CAP0402: Mfr_Name: MURATA; Mfr_Part_Number: GRM155R71C104KA88D; TOL: 10%; Voltage: 16V
C38-C41 = CAP0402: Mfr_Name: Samsung Electro-Mechanics America, Inc; Mfr_Part_Number: CL05B224KO5NNNC; TOL: +/-10%; Voltage: 10V
C168 = CAP_NP_0: Mfr_Name: AVX; Mfr_Part_Number: 06035C103JAT2A; TOL: 5%; VOLTAGE: 50V
JP1 = Jumper_1x3_smt: Mfr_Name: SAMTEC; Mfr_Part_Number: TSW-103-07-L-S; Note: SHUNT 2-3; PART_NUMBER: 929400-01-36; TI_Silktext: PDN
JP2-JP5 = JUMPER_1x2_100: Note: SHORTED
R57 R87 = RES0603: Mfr_Name: Panasonic; Mfr_Part_Number: ERJ-2RKF1001X; TOL: 1%; Wattage: 1/16W
R58 = R_4: Mfr_Name: Panasonic; Mfr_Part_Number: ERJ-2RKF1002X; TOL: 1%; Wattage: 1/10W
SHN1-SHN7 = SHUNT_HEADER
SW1 = SW_PUSHBUTTON_1: CLASS: DISCRETE; Manufacturer: C & K Switch; Mfr_Name: ITT Industries/C&K Div; Mfr_Part_Number: PTS635SL43 LFS; PART_NUMBER: PTS635SL43; TI_Silktext: ADC RESET
TP1 = TP_THVT_060_RND-RED: TI_SILKTEXT: VCMOUT
U1 = ADC32XX: Mfr_Part_Number: AD32XX
C160 C210 = CAP_X2Y: X2Y, 0.22uF, +/-20%, 10V, X5R(0603); Mfr_Name: Johanson Dielectrics Inc; Mfr_Part_Number: 160X14X224MV4T; Package: SMD; Terasic_Prt: MP03-16112R; Type: Capacitor
C180 C205 = CAP_0402_33pF: Mfr_Name: Kemet; Mfr_Part_Number: CBR04C130F5GAC
C181 C206 = CAP_0402_18pF: Mfr_Name: MURATA; Mfr_Part_Number: GRM1535C1H560JDD5D
C58 C64 C187 C195 C199 C207 C208 = CAP_NP_0: Mfr_Name: TDK CORPORATION; Mfr_Part_Number: C1608X7R1E105K080AB; TOL: 10%; VOLTAGE: 25V
C59 C60 C62 C65 C70 C72 C188 C190 C198 C200 = CAPACITOR_NP_1: Mfr_Name: MURATA; Mfr_Part_Number: GRM155R71C104KA88D; TOL: 10%; Voltage: 16V
C189 C209 = CAP_0603_1000pF: Mfr_Name: AVX CORP.; Mfr_Part_Number: 0603YC103KAT2A
D3 D4 = DIODE_BAV99: Mfr_Name: FAIRCHILD SEMICONDUCTOR
FB8 FB9 = FERRITE_BEAD: Mfr_Name: MURATA; Mfr_Part_Number: BLM21AG102SN1D
L23 L24 L26 L27 = IND0603: Mfr_Name: COILCRAFT; Mfr_Part_Number: 0603CS-R15XGLU
R92 R93 R127 R128 = Res_0402_249: Mfr_Part_Number: ERJ-2RKF2050X
R94 R95 R129 R130 = Res_0402_249: Mfr_Part_Number: ERJ-2RKF4990X
R96 R98 R131 R133 = RES0402: Mfr_Name: VISHAY DALE; Mfr_Part_Number: CRCW040259R0FKED
R97 R132 = RES0603: GROUP: Not Installed; Mfr_Name: Panasonic; Mfr_Part_Number: ERJ-2RKF49R9X; TOL: 1%; Wattage: 1/10W
R101 R134 R154 R156 = Res_0402_249: Mfr_Part_Number: ERJ-2RKF2870X
R104 R149 = RES0603: GROUP: Not Installed; Mfr_Name: Panasonic; Mfr_Part_Number: ERJ-2RKF7320X; TOL: 1%; Wattage: 1/10W
R106 R122 = RES0603: Mfr_Name: VISHAY/DALE; Mfr_Part_Number: CRCW06032R00FNEA
R107 R123 = RES0603: Mfr_Name: VISHAY/DALE; Mfr_Part_Number: CRCW060320K0FKEA
R108 = RES0603: GROUP: Not Installed; Mfr_Name: Panasonic; Mfr_Part_Number: ERJ-2RKF49R9X; Note: DNI; TI_Silktext: Amp Power Down A; TOL: 1%; Wattage: 1/10W
R109 R110 R125 R126 = Res_0402_249: Mfr_Part_Number: ERJ-2RKF44R2X
R124 = RES0603: GROUP: Not Installed; Mfr_Name: Panasonic; Mfr_Part_Number: ERJ-2RKF49R9X; Note: DNI; TI_Silktext: Amp Power Down B; TOL: 1%; Wattage: 1/10W
R150 R152 = RES0603: GROUP: Not Installed; Mfr_Name: Panasonic; Mfr_Part_Number: ERJ-2RKF1102X; Note: DNI; TOL: 1%; Wattage: 1/10W
R151 R153 = RES0603: GROUP: Not Installed; Mfr_Name: Panasonic; Mfr_Part_Number: ERJ-2RKF1000X; Note: DNI; TOL: 1%; Wattage: 1/10W
RSHN1 RSHN2 = SHUNT_RES: Mfr_Part_Number: ERJ-3GEY0R00V
SJP1 SJP2 = Jumper_1x3_smt: Mfr_Name: N/A; Mfr_Part_Number: SMD PADS; Note: SHUNT 1-2; TI_Silktext: Coupling Options
U7 U10 = THS4541RGT
C44 C47 = CAP0402: Mfr_Name: MURATA; Mfr_Part_Number: GRM155R71C104KA88D; Note: DNI; TOL: 10%; Voltage: 16V
C174 = CAP0603: Mfr_Name: Panasonic; Mfr_Part_Number: ERJ-2GE0R00X; TOL: 5%; Voltage: <Voltage>
J9 = SMA-THVT_142-0701-201_REC: TI_Silktext: CLK_INP
J10 = SMA-THVT_142-0701-201_REC: Note: DNI; TI_Silktext: CLK_INM
J11 = SMA-THVT_142-0701-201_REC: TI_Silktext: SYSREF_INP
J12 = SMA-THVT_142-0701-201_REC: Note: DNI; TI_Silktext: SYSREF_INM
R59 R63 = RES0603: GROUP: Not Installed; Mfr_Name: Yageo; Mfr_Part_Number: RC0402FR-0749R9L; Note: DNI; PART_NUMBER: ERJ-3EKF49R9V; TOL: 1%; Wattage: 1/16W
R60 R61 R64 R66 = RES0603: GROUP: Not Installed; Mfr_Name: Panasonic; Mfr_Part_Number: ERJ-2RKF1000X; TOL: 1%; Wattage: 1/10W
T9 T10 = XFMR_6_JTX-4-10T: Mfr_Name: Minicircuits
Z_SCREW1-Z_SCREW4 = STANDOFF-SCREW: Mfr_Part_Number: PMSSS 440 0038 PH; Note: SCREW FOR STANDOFF
Z_STANDOFF1-Z_STANDOFF4 = STANDOFF: Mfr_Name: Keystone
J13 = CON_SMVT_120POS_QTH_SAMTEC
C55 = CAP_NP_0: Mfr_Name: MURATA; Mfr_Part_Number: GRM32ER61A476KE20L; TOL: 10%; VOLTAGE: 10V
C56 C63 = CAP_1210_22uF: Mfr_Part_Number: C3225X5R1A226M230AA
C57 C67 C197 = CAP_NP_1: Mfr_Name: Samsung; Mfr_Part_Number: CL21B106KOQNNNE; TOL: 10%; VOLTAGE: 25V
C61 = CAP_1206_2.2uF: Mfr_Name: Samsung; Mfr_Part_Number: CL21B106KOQNNNE; TOL: 10%; VOLTAGE: 25V
C66 C68 C191 C196 = CAPACITOR_NP_1: Mfr_Name: MURATA; Mfr_Part_Number: GRM155R71H103KA88D; TOL: 10%; Voltage: 16V
C71 C192 = CAP_NP_1: Mfr_Name: TDK CORPORATION; Mfr_Part_Number: C1608X7R1E105K080AB; TOL: 10%; VOLTAGE: 25V
C73 C193 = CAP0201: Mfr_Name: MURATA; Mfr_Part_Number: GRM32ER61A476KE20L; TOL: 10%; VOLTAGE: 10V
C74 = CAP_NP_0: Mfr_Name: Yageo; Mfr_Part_Number: C1608X7R1E105K; TOL: 10%; VOLTAGE: 25V
D1 = LED_GREEN_1206: TI_SILKTEXT: PWR
D2 = MBRB2515L_5
F1 = FUSE_0: Mfr_Name: TE Connectivity; Mfr_Part_Number: 1206SFF200F/63-2; Note: DNI
FB1 FB2 = FERRITE_BEAD: Mfr_Name: Taiyo Yuden; Mfr_Part_Number: FBMJ3216HM600-T
FB3 = BEAD_NFM31P: Mfr_Name: Murata; Mfr_Part_Number: NFM31PC276B0J3L; Tolerance: 20%
FB4 FB5 FB7 = FERRITE_BEAD: Mfr_Name: Panasonic; Mfr_Part_Number: BLM41PG102SN1L
J15 = CONN_JACK_PWR: Mfr_Name: SWITCHCRAFT; Mfr_Part_Number: RAPC722X
JP6 = SMD_JUMPER_1x3: Mfr_Name: SAMTEC; Mfr_Part_Number: HTSW-103-07-G-S; Note: SHUNT 1-2
JP7 = SMD_JUMPER_1x3: Mfr_Name: SAMTEC; Mfr_Part_Number: HTSW-103-07-G-S; Note: SHUNT 1-2; TI_Silktext: PDN
L17 = IND_POWER_1.5uH: Mfr_Name: Coilcraft; Mfr_Part_Number: XFL3012-102ME
Q1 = CSD18532Q5B
R75 = Res_0402_1k
R76 R81 = Res_0402_1k: Mfr_Part_Number: ERJ-3GEY0R00V
R77 R80 = Res_0402_1k: Mfr_Part_Number: ERJ-3GEY0R00V; Note: DNI
R78 = Res_0402_1k: Mfr_Part_Number: ERJ-2RKF1053X
R79 = Res_0402_1k: Mfr_Part_Number: ERJ-2RKF1433X; Note: DNI
R82 = Res_0402_1k: Mfr_Part_Number: ERJ-2RKF2002X
R83 R115 = R_1: CLASS: DISCRETE; Mfr_Name: Vishay Dale; Mfr_Part_Number: CRCW040225K5FKED; TOL: 1%
R67-R70 R84 R85 R114 R116 R119 = R: Mfr_Name: Panasonic; Mfr_Part_Number: ERJ-2GE0R00X; Note: DNI; TOL: 5%
RS1 RS2 = R: Mfr_Name: Vishay Dale; Mfr_Part_Number: WSL0805R2000FEA18; Note: Rs; TOL: 1%
TP4 = TESTLOOP_BLACK: Mfr_Name: Keystone; Mfr_Part_Number: 5010; TI_SILKTEXT: +5V
TP5 = TESTLOOP_BLACK: Mfr_Name: KEYSTONE; Mfr_Part_Number: 5011; TI_SILKTEXT: GND
TP8 = TESTPOINT_BLUE: Mfr_Part_Number: 5010
TP9-TP12 = TESTLOOP_BLACK: Mfr_Name: KEYSTONE; Mfr_Part_Number: 5006; TI_SILKTEXT: GND
U3 = TPS2400: Mfr_Name: Texas Instruments; Mfr_Part_Number: TPS2400DBVT
U4 = TPS62080_SON8: Mfr_Name: Texas Instruments; Mfr_Part_Number: TPS62080DSGT
U5 U8 = TPS7A4700: Mfr_Name: Texas Instruments; Mfr_Part_Number: TPS7A4700RGWT
U6 = INA138: Mfr_Name: Texas Instruments; Mfr_Part_Number: INA138NA/250
U9 = INA138: Mfr_Name: Texas Instruments; Mfr_Part_Number: INA138NA
C49 = CAP0603: Mfr_Name: Murata; Mfr_Part_Number: GRM188R71C103KA01D
C50 C54 = CAP_NP_0: Mfr_Name: Yageo; Mfr_Part_Number: CC0402KRX5R7BB104; TOL: 10%; VOLTAGE: 16V
C51 = CAP_POL-B_10uF_10V: Mfr_Name: AVX; Mfr_Part_Number: TAJA475K020R; PART_NUMBER: AVX TAJA475K020RNJ; TOL: 10%; VOLTAGE: 20V
C52 C53 = CAP0603: Mfr_Name: Kemet; Mfr_Part_Number: C0603C470J5GACTU
J14 = USB_MINI_AB_MNE20-5G5P10: Mfr_Name: Molex Inc.; Mfr_Part_Number: 678038020; TI_SILKTEXT: USB
R71-R74 = R: Mfr_Name: Panasonic; Mfr_Part_Number: ERJ-2RKF22R0X; TOL: 1%
U2 = FT245RL_0: Mfr_Name: FTDI Chip

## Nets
1.8V: JP6.3(Pin3) JP7.3(Pin3)
2.8V_IN: C67.1 C68.2 C70.2 JP6.1(Pin1) U5.13(EN) U5.15(IN2) U5.16(IN1)
5.0V_IN: D2.4 F1.1 J15.1 Q1.5(D5) Q1.6(D6) Q1.7(D7) Q1.8(D8) TP4.1(TP) U3.5(VIN)
5VIN: C49.1 C57.1 C58.1 C59.2 C60.2 C61.1 C190.2 C191.2 C197.1 FB1.2 FB2.1 R75.1 R76.1 R77.1 U4.8(VIN) U6.5(V+) U8.13(EN) U8.15(IN2) U8.16(IN1) U9.5(V+)
+VCC: FB8.2 FB9.2 RS2.1 U8.3(SENSE) U9.4(VIN-)
AVDD1.8V: C29.1 C30.1 C31.1 C32.1 C33.1 C34.1 C35.1 C36.1 C37.1 C169.1 C170.1 FB5.1 U1.6(AVDD) U1.7(AVDD) U1.8(AVDD) U1.9(AVDD) U1.12(AVDD) U1.17(AVDD) U1.20(AVDD) U1.25(AVDD) U1.28(AVDD) U1.29(AVDD) U1.30(AVDD)
DVDD1.8V: C38.1 C39.1 C40.1 C41.1 FB4.1 JP1.1(Pin1) R57.1 R87.1 U1.2(DVDD) U1.4(DVDD) U1.33(DVDD) U1.35(DVDD)
GND: C3.1 C4.1 C5.1 C6.1 C10.1 C11.1 C12.1 C13.1 C29.2 C30.2 C31.2 C32.2 C33.2 C34.2 C35.2 C36.2 C37.2 C38.2 C39.2 C40.2 C41.2 C42.2 C45.2 C48.2 C49.2 C50.2 C51.2 C52.2 C53.2 C54.2 C55.2 C56.1 C57.2 C58.2 C59.1 C60.1 C61.2 C62.1 C63.1 C64.2 C65.1 C66.1 C67.2 C68.1 C69.2 C70.1 C71.2 C72.1 C73.2 C74.2 C160.G1 C160.G2 C168.2 C169.2 C170.2 C173.2 C174.2 C187.2 C188.1 C189.2 C190.1 C191.1 C192.2 C193.2 C194.2 C195.2 C196.1 C197.2 C198.1 C199.2 C200.1 C207.2 C208.2 C209.2 C210.G1 C210.G2 D1.2(CATHODE) D2.1 D2.3 D3.1 D4.1 FB3.2 J1.2(SHIELD3) J1.3(SHIELD4) J1.4(SHIELD1) J1.5(SHIELD2) J2.2(SHIELD3) J2.3(SHIELD4) J2.4(SHIELD1) J2.5(SHIELD2) J3.2(SHIELD3) J3.3(SHIELD4) J3.4(SHIELD1) J3.5(SHIELD2) J4.2(SHIELD3) J4.3(SHIELD4) J4.4(SHIELD1) J4.5(SHIELD2) J9.2(GND) J9.3(GND) J9.4(GND) J9.5(GND) J10.2(GND) J10.3(GND) J10.4(GND) J10.5(GND) J11.2(GND) J11.3(GND) J11.4(GND) J11.5(GND) J12.2(GND) J12.3(GND) J12.4(GND) J12.5(GND) J13.5 J13.6 J13.11 J13.12 J13.17 J13.18 J13.23 J13.24 J13.29 J13.30 J13.35 J13.36 J13.41 J13.42 J13.47 J13.48 J13.53 J13.54 J13.59 J13.60 J13.61 J13.62 J13.67 J13.68 J13.73 J13.74 J13.79 J13.80 J13.85 J13.86 J13.91 J13.92 J13.97 J13.98 J13.103 J13.104 J13.109 J13.110 J13.116 J13.121(GND) J13.122(GND) J13.123(GND) J13.124(GND) J13.125(GND) J13.126(GND) J13.127(GND) J13.128(GND) J14.5(GND) J14.6(GND1) J14.7(GND2) J14.8(GND3) J14.9(GND4) J15.2 J15.3 JP1.3(Pin3) R7.2 R11.2 R20.2 R25.2 R58.2 R59.2 R62.2 R63.2 R65.2 R80.2 R81.2 R82.2 R83.2 R84.1 R85.1 R86.2 R96.2 R98.2 R108.1 R113.1 R114.1 R115.2 R116.1 R117.1 R118.1 R119.1 R124.1 R131.2 R133.2 R151.2 R153.2 R155.2 R157.2 SJP1.1(Pin1) SJP2.1(Pin1) TP5.1(TP) TP9.1(TP) TP10.1(TP) TP11.1(TP) TP12.1(TP) U1.1(GND) U1.3(GND) U1.5(GND) U1.32(GND) U1.34(GND) U1.36(GND) U1.49(THERMPAD) U2.7(GND) U2.18(GND) U2.21(GND) U2.25(AGND) U2.26(TEST) U3.2(GND) U4.2(GND) U4.9(THERMPAD) U5.7(GND) U5.10(0P4V) U5.21(PWRPAD) U6.2(GND) U7.13(VS1-) U7.14(VS2-) U7.15(VS3-) U7.16(VS4-) U7.17(pwrpad) U8.7(GND) U8.21(PWRPAD) U9.2(GND) U10.13(VS1-) U10.14(VS2-) U10.15(VS3-) U10.16(VS4-) U10.17(pwrpad)
A_INM: J2.1(CENTER) R8.1 R136.2
A_INP: J1.1(CENTER) R4.1 R135.1
ADCAM: C181.2 L24.2 R101.1 R121.1
ADCAP: C181.1 L23.2 R120.2 R156.2
ADCBM: C206.1 L26.2 R144.1 R154.2
ADCBP: C206.2 L27.2 R134.1 R141.2
AINM: R14.2 R121.2 U1.10(INP_A)
AINP: R3.2 R120.1 U1.11(INM_A)
AMPAINM: R93.1 R96.1 R97.2 R136.1
AMPAINP: R92.1 R98.1 R135.2
AMPBINM: R127.1 R133.1 R138.1
AMPBINP: R128.1 R131.1 R132.2 R137.2
B_INM: J3.1(CENTER) R23.1 R137.1
B_INP: J4.1(CENTER) R18.1 R138.2
BINM: R142.2 R144.2 U1.27(INP_B)
BINP: R139.2 R141.1 U1.26(INM_B)
CLKINM: R61.1 T9.4(secondary) U1.19(CLKM)
CLKINP: R60.2 T9.6(secondary_dot) U1.18(CLKP)
CLOCK_INM: C44.2 J10.1(CENTER)
CLOCK_INP: C43.2 J9.1(CENTER)
DA0M: J13.44 U1.48(DA0M)
DA0P: J13.46 U1.47(DA0P)
DA1M: J13.50 U1.46(DA1M)
DA1P: J13.52 U1.45(DA1P)
DB0M: J13.70 U1.40(DB0M)
DB0P: J13.72 U1.39(DB0P)
DB1M: J13.76 U1.38(DB1M)
DB1P: J13.78 U1.37(DB1P)
DCLKM: J13.56 U1.44(DCLKM)
DCLKP: J13.58 U1.43(DCLKP)
FCLKM: J13.64 U1.42(FCLKM)
FCLKP: J13.66 U1.41(FCLKP)
FPGA_CSEL: J13.115 R70.1
FPGA_SCLK: J13.119 R67.1
FPGA_SDI: J13.117 R68.1
FPGA_SDO: J13.113 R69.1
FTDI_VCCIO1.8V: FB7.1 U2.4(VCCIO)
PDA: C188.2 R107.2 R108.2 U7.12(PD)
PDB: C200.2 R123.2 R124.2 U10.12(PD)
PDN: JP1.2(Pin2) U1.31(PDN)
RESET: C168.1 R58.1 SW1.1 U1.21(RESET)
SCLK: JP2.2 R72.1
SDATA: JP3.2 R71.1
SDOUT: JP5.2 R73.1
SEN: JP4.2 R74.1
SYSREF_INM: C47.2 J12.1(CENTER)
SYSREF_INP: C46.2 J11.1(CENTER)
SYSREFM: R66.1 T10.4(secondary) U1.23(SYSREFM)
SYSREFP: R64.2 T10.6(secondary_dot) U1.22(SYSREFP)
U5_SENSE: FB4.2 FB5.2 RS1.1 U5.3(SENSE) U6.4(VIN-)
VAMPA: C160.A C160.B D3.2 R106.2 R107.1 R150.2 U7.5(VS1+) U7.6(VS2+) U7.7(VS3+) U7.8(VS4+)
VAMPB: C210.A C210.B D4.2 R122.2 R123.1 R152.2 U10.5(VS1+) U10.6(VS2+) U10.7(VS3+) U10.8(VS4+)
VCM: C4.2 C11.2 C42.1 L2.2 L6.2 R104.1 R149.1 TP1.1(TP) U1.24(VCM)
VCM_AMPA: C209.1 R149.2 R150.1 R151.1 U7.9(Vocm)
VCM_AMPB: C189.1 R104.2 R152.1 R153.1 U10.9(Vocm)
N16255310: C5.2 T1.2(secondary_ct) T1.5(NC)
N16255380: T1.6(primary_dot) T2.4(primary)
N16255412: T1.4(primary) T2.6(primary_dot)
N16255546: C6.2 T2.2(secondary_ct) T2.5(NC)
N16275326: C12.2 T3.2(secondary_ct) T3.5(NC)
N16275406: C14.1 T4.1(secondary_dot)
N16275410: T3.4(primary) T4.6(primary_dot)
N16275430: T3.6(primary_dot) T4.4(primary)
N16275564: C13.2 T4.2(secondary_ct) T4.5(NC)
N17995731: C7.1 T2.3(secondary)
N18036747: R4.2 R7.1 T1.3(secondary)
N18037025: R8.2 R11.1 T1.1(secondary_dot)
N18037341: R18.2 R20.1 T3.3(secondary)
N18145356: C44.1 R62.1 T9.1(primary)
N18145361: C43.1 R59.1 T9.3(primary_dot)
N18152532: C1.1 T2.1(secondary_dot)
N18152657: C8.1 T4.3(secondary)
N18154317: JP2.1 U1.13(SCLK)
N18154319: JP5.1 U1.16(SDOUT)
N18154320: JP4.1 R57.2 U1.15(SEN)
N18154541: JP3.1 U1.14(SDATA)
N18158256: C50.1 C51.1 FB1.1 U2.20(VCC)
N18158298: R69.2 R73.2 U2.3(D2)
N18158304: R67.2 R72.2 U2.1(D0)
N18158332: C53.1 J14.2(D-) U2.16(USBDM)
N18158362: C54.1 U2.17(3V3OUT)
N18158372: C52.1 J14.3(D+) U2.15(USBDP)
N18158488: R68.2 R71.2 U2.5(D1)
N18172592: R23.2 R25.1 T3.1(secondary_dot)
N18176897: C3.2 L2.1 R5.2 R9.1
N18176915: C2.1 L3.2 R6.2
N18176926: C2.2 L3.1 R10.1
N18176961: R2.2 R3.1 R6.1
N18176965: R10.2 R13.2 R14.1
N18176992: L1.1 R1.2 R2.1 R5.1
N18176994: L4.1 R9.2 R12.2 R13.1
N18177028: C1.2 L1.2 R1.1
N18177046: C7.2 L4.2 R12.1
N18177748: C10.2 L6.1 R21.2 R22.1
N18177758: C9.1 L7.2 R19.2
N18177777: C9.2 L7.1 R24.1
N18177812: R16.2 R19.1 R139.1
N18177816: R24.2 R27.2 R142.1
N18177835: L5.1 R15.2 R16.1 R21.1
N18177837: L8.1 R22.2 R26.2 R27.1
N18177879: C8.2 L5.2 R15.1
N18177897: C14.2 L8.2 R26.1
N18182829: C47.1 R65.1 T10.1(primary)
N18182834: C46.1 R63.1 T10.3(primary_dot)
N18184820: R76.2 R80.1 U4.1(EN)
N18184826: R77.2 R81.1 U4.3(MODE)
N18184858: L17.1 U4.7(SW)
N18184878: C62.2 C63.2 FB3.1 L17.2 R78.1 R79.1 U4.5(VOS)
N18184911: R78.2 R79.2 R82.1 U4.4(FB)
N18184929: C66.2 C72.2 FB7.2 JP7.2(Pin2) RS1.2 U6.3(VIN+)
N18184992: C55.1 C56.2 F1.2 FB2.2 Q1.1(S1) Q1.2(S2) Q1.3(S3)
N18185086: C69.1 C71.1 C73.1 JP7.1(Pin1) U5.1(OUT1) U5.20(OUT2)
N18185106: C74.1 U5.14(NR)
N18185155: R84.2 U5.12(0P1V)
N18185175: R85.2 U5.11(0P2V)
N18185335: C64.1 C65.2 FB3.3 JP6.2(Pin2)
N18185416: R83.1 TP8.1(TP) U6.1(OUT)
N18185709: Q1.4(G) U3.4(GATE)
N18185817: D1.1(ANODE) R75.2
N18186843: R70.2 R74.2 U2.11(D3)
N18187243: J14.4(ID) R86.1
N18187932: R87.2 SW1.2
N18195117: C45.1 R60.1 R61.2
N18195272: C173.1 T9.2(primary_ct) T9.5(secondary_ct)
N18195497: C48.1 R64.1 R66.2
N18195560: C174.1 T10.2(primary_ct) T10.5(secondary_ct)
N18236051: C180.1 L23.1 R109.2
N18236057: C180.2 L24.1 R110.2
N18238916: C187.1 FB8.1 R106.1
N18248026: R110.1 U7.10(VOUT+)
N18248246: R109.1 U7.11(VOUT-)
N18248498: R93.2 R95.2 U7.3(VIN-)
N18248506: R95.1 U7.4(FB+)
N18248596: D3.3 R92.2 R94.2 U7.2(VIN+)
N18248639: R94.1 U7.1(FB-)
N18254985: C192.1 C193.1 C194.1 C196.2 C198.2 RS2.2 U8.1(OUT1) U8.20(OUT2) U9.3(VIN+)
N18255095: C195.1 U8.14(NR)
N18255144: R114.2 U8.12(0P1V)
N18255168: R113.2 U8.11(0P2V)
N18255172: R116.2 U8.10(0P4V)
N18255251: R115.1 U9.1(OUT)
N18258500: R117.2 U8.9(0P8V)
N18258503: R118.2 U8.8(1P6V)
N18258506: R119.2 U8.6(3P2V)
N18271567: C199.1 FB9.1 R122.1
N18273924: C205.1 L26.1 R125.2
N18273934: C205.2 L27.1 R126.2
N18274097: R126.1 U10.10(VOUT+)
N18274103: R125.1 U10.11(VOUT-)
N18274115: R128.2 R130.2 U10.3(VIN-)
N18274119: R130.1 U10.4(FB+)
N18274129: D4.3 R127.2 R129.2 U10.2(VIN+)
N18274135: R129.1 U10.1(FB-)
N18283030: C207.1 SJP1.3(Pin3)
N18283930: R97.1 SJP1.2(Pin2)
N18284096: C208.1 SJP2.3(Pin3)
N18284104: R132.1 SJP2.2(Pin2)
N18358536: R134.2 R154.1 R155.1
N18359182: R101.2 R156.1 R157.1

Not connected (* = marked no-connect by the designer): D2 2*; J13 1 2 3 4 7 8 9 10 13 14 15 16 19 20 21 22 25 26 27 28 31 32 33 34 37 38 39 40 43 45 49 51 55 57 63 65 69 71 75 77 81 82 83 84 87 88 89 90 93 94 95 96 99 100 101 102 105 106 107 108 111 112 114 118 120; J14 1(VBUS); U2 2(D4)* 6(D7)* 8(NC1)* 9(D5)* 10(D6)* 12(PWREN)* 13(RD)* 14(WR)* 19(RESET)* 22(TXE)* 23(RXF)* 24(NC2)* 27(OSCI)* 28(OSCO)*; U3 1(NC1)* 3(NC3)*; U4 6(PG); U5 2(NC1)* 4(6P4V2)* 5(6P4V1)* 6(3P2V)* 8(1P6V)* 9(0P8V)* 17(NC2)* 18(NC3)* 19(NC4)*; U8 2(NC1)* 4(6P4V2)* 5(6P4V1)* 17(NC2)* 18(NC3)* 19(NC4)*

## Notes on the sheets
sheet 1
- 40M Bessel Filter
- +0.95V
- 2 to 3 for AC coupled Vin
- 2 to 1 for DC coupled Vin
- 40M Bessel Filter
- +0.95V
- 2 to 3 for AC coupled Vin
- 2 to 1 for DC coupled Vin
sheet 2
- ADC32XX
  Channel A and B Input
         Sheet 2
- ADC32XX
   Sheet 3
- Amplifier
    Sheet 4
- Clock Input
    Sheet 5
- LVDS Outputs
       Sheet 6
- USB Interface
    Sheet 8
- Power Supplies
      Sheet 7
- Engineer:
- Ken Chan
- PCB:
- Loan Nguyen
sheet 3
- SHARED PAD
- SHARED PAD
- SHARED PAD
- 11pF caps in parallel to avoid stub
  Install 82nH in high frequency mode
- 100 OHM DIFF
- SHARED PAD
- SHARED PAD
- SHARED PAD
- SHARED PAD
- SHARED PAD
- SHARED PAD
- 11pF caps in parallel to avoid stub
  Install 82nH in high frequency mode
- 100 OHM DIFF
- SHARED PAD
- SHARED PAD
- SHARED PAD
- 12500 TI Boulevard. Dallas, Texas 75243
- DNI = DO NOT INSTALL
sheet 4
- DNI = DO NOT INSTALL
- MASTER
- DUT
- 12500 TI Boulevard. Dallas, Texas 75243
sheet 5
- MECHANICAL PARTS
sheet 6
- 12500 TI Boulevard. Dallas, Texas 75243
sheet 8
- U4 output = 2.8V
  For 1.8V, install R79
- Pay close attention to
  feedback node in layout
- Keep sense line short
- VREF = 1.4V
- Keep sense line short
- 12500 TI Boulevard. Dallas, Texas 75243
- Default output is 1.4V+0.2+0.8+1.6 = 4V
- DNI = DO NOT INSTALL
